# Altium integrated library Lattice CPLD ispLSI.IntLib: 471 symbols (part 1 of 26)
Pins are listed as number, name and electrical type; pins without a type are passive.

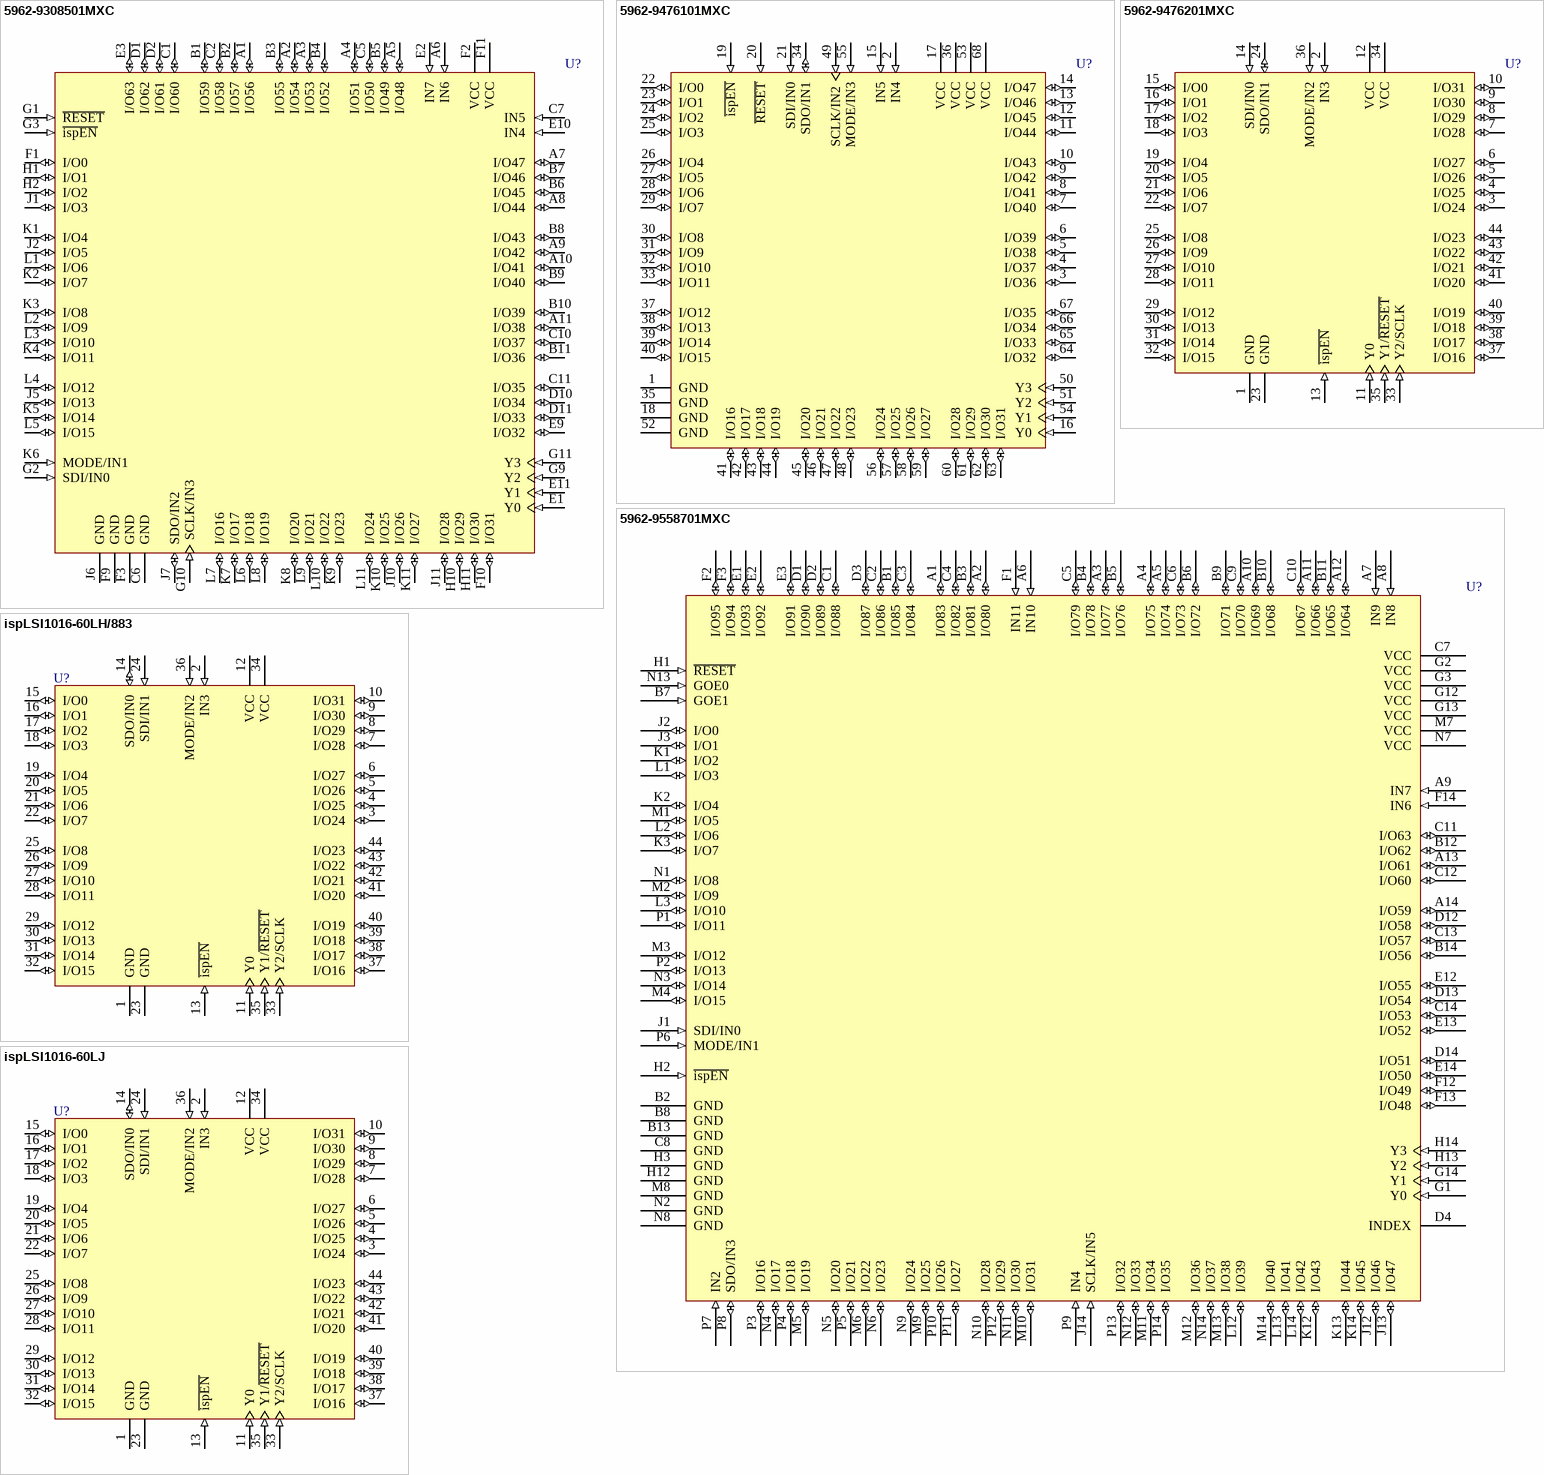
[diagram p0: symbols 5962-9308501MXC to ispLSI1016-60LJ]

## 5962-9308501MXC
designator U?
In-System Programmable High-Density PLD; Note: Pins G2, K6, J7 and G10 have dual function capability.; Note: SMD Number shown, corresponds to Device
footprint CPGA84 (PGA, 85-Leads, Body 29.5x29.5mm, Pitch 2.54mm)
3D model 1032-CPGA84 (85-Pin Pin Grid Array 2.54 mm Pitch)
pins: A1 I/O56 (io), A2 I/O54 (io), A3 I/O53 (io), A4 I/O51 (io), A5 I/O48 (io), A6 IN6 (in), A7 I/O47 (io), A8 I/O44 (io), A9 I/O42 (io), A10 I/O41 (io), A11 I/O38 (io), B1 I/O59 (io), B2 I/O57 (io), B3 I/O55 (io), B4 I/O52 (io), B5 I/O49 (io), B6 I/O45 (io), B7 I/O46 (io), B8 I/O43 (io), B9 I/O40 (io), B10 I/O39 (io), B11 I/O36 (io), C1 I/O60 (io), C2 I/O58 (io), C5 I/O50 (io), C6 GND (power), C7 IN5 (in), C10 I/O37 (io), C11 I/O35 (io), D1 I/O62 (io), D2 I/O61 (io), D10 I/O34 (io), D11 I/O33 (io), E1 Y0 (in), E2 IN7 (in), E3 I/O63 (io), E9 I/O32 (io), E10 IN4 (in), E11 Y1 (in), F1 I/O0 (io), F2 VCC (power), F3 GND (power), F9 GND (power), F10 I/O31 (io), F11 VCC (power), G1 ~{RESET} (in), G2 SDI/IN0 (in), G3 ~{ispEN} (in), G9 Y2 (in), G10 SCLK/IN3 (in), G11 Y3 (in), H1 I/O1 (io), H2 I/O2 (io), H10 I/O29 (io), H11 I/O30 (io), J1 I/O3 (io), J2 I/O5 (io), J5 I/O13 (io), J6 GND (power), J7 SDO/IN2 (io), J10 I/O26 (io), J11 I/O28 (io), K1 I/O4 (io), K2 I/O7 (io), K3 I/O8 (io), K4 I/O11 (io), K5 I/O14 (io), K6 MODE/IN1 (in), K7 I/O17 (io), K8 I/O20 (io), K9 I/O23 (io), K10 I/O25 (io), K11 I/O27 (io), L1 I/O6 (io), L2 I/O9 (io), L3 I/O10 (io), L4 I/O12 (io), L5 I/O15 (io), L6 I/O18 (io), L7 I/O16 (io), L8 I/O19 (io), L9 I/O21 (io), L10 I/O22 (io), L11 I/O24 (io)

## 5962-9476101MXC
designator U?
In-System Programmable High-Density PLD; Note: Pins 21, 34, 49 and 55 have dual function capability.; Note: SMD Number shown, corresponds to Device
footprint JLCC68_N (Leaded Chip Carrier, 68-Leads, Body 24x24mm, Pitch 1.27mm, IPC Medium Density)
footprint JLCC68_L (Leaded Chip Carrier, 68-Leads, Body 24x24mm, Pitch 1.27mm, IPC High Density)
footprint JLCC68_M (Leaded Chip Carrier, 68-Leads, Body 24x24mm, Pitch 1.27mm, IPC Low Density)
3D model 1024-JLCC68 (68-Pin Leaded Chip Carrier 1.27 mm Pitch)
pins: 1 GND (power), 2 IN4 (in), 3 I/O36 (io), 4 I/O37 (io), 5 I/O38 (io), 6 I/O39 (io), 7 I/O40 (io), 8 I/O41 (io), 9 I/O42 (io), 10 I/O43 (io), 11 I/O44 (io), 12 I/O45 (io), 13 I/O46 (io), 14 I/O47 (io), 15 IN5 (in), 16 Y0 (in), 17 VCC (power), 18 GND (power), 19 ~{ispEN} (in), 20 ~{RESET} (in), 21 SDI/IN0 (in), 22 I/O0 (io), 23 I/O1 (io), 24 I/O2 (io), 25 I/O3 (io), 26 I/O4 (io), 27 I/O5 (io), 28 I/O6 (io), 29 I/O7 (io), 30 I/O8 (io), 31 I/O9 (io), 32 I/O10 (io), 33 I/O11 (io), 34 SDO/IN1 (io), 35 GND (power), 36 VCC (power), 37 I/O12 (io), 38 I/O13 (io), 39 I/O14 (io), 40 I/O15 (io), 41 I/O16 (io), 42 I/O17 (io), 43 I/O18 (io), 44 I/O19 (io), 45 I/O20 (io), 46 I/O21 (io), 47 I/O22 (io), 48 I/O23 (io), 49 SCLK/IN2 (in), 50 Y3 (in), 51 Y2 (in), 52 GND (power), 53 VCC (power), 54 Y1 (in), 55 MODE/IN3 (in), 56 I/O24 (io), 57 I/O25 (io), 58 I/O26 (io), 59 I/O27 (io), 60 I/O28 (io), 61 I/O29 (io), 62 I/O30 (io), 63 I/O31 (io), 64 I/O32 (io), 65 I/O33 (io), 66 I/O34 (io), 67 I/O35 (io), 68 VCC (power)

## 5962-9476201MXC
designator U?
In-System Programmable High-Density PLD; Note: Pins 14, 24, 33 and 36 have dual function capability.; Note: SMD Number shown, corresponds to Device ispLSI 1016-60LH/883
footprint JLCC44_N (Leaded Chip Carrier, 44-Leads, Body 16.3x16.3mm, Pitch 1.27mm, IPC Medium Density)
footprint JLCC44_L (Leaded Chip Carrier, 44-Leads, Body 16.3x16.3mm, Pitch 1.27mm, IPC High Density)
footprint JLCC44_M (Leaded Chip Carrier, 44-Leads, Body 16.3x16.3mm, Pitch 1.27mm, IPC Low Density)
3D model 1016-JLCC44 (44-Pin Leaded Chip Carrier 1.27 mm Pitch)
pins: 1 GND (power), 2 IN3 (in), 3 I/O24 (io), 4 I/O25 (io), 5 I/O26 (io), 6 I/O27 (io), 7 I/O28 (io), 8 I/O29 (io), 9 I/O30 (io), 10 I/O31 (io), 11 Y0 (in), 12 VCC (power), 13 ~{ispEN} (in), 14 SDI/IN0 (in), 15 I/O0 (io), 16 I/O1 (io), 17 I/O2 (io), 18 I/O3 (io), 19 I/O4 (io), 20 I/O5 (io), 21 I/O6 (io), 22 I/O7 (io), 23 GND (power), 24 SDO/IN1 (io), 25 I/O8 (io), 26 I/O9 (io), 27 I/O10 (io), 28 I/O11 (io), 29 I/O12 (io), 30 I/O13 (io), 31 I/O14 (io), 32 I/O15 (io), 33 Y2/SCLK (in), 34 VCC (power), 35 Y1/~{RESET} (in), 36 MODE/IN2 (in), 37 I/O16 (io), 38 I/O17 (io), 39 I/O18 (io), 40 I/O19 (io), 41 I/O20 (io), 42 I/O21 (io), 43 I/O22 (io), 44 I/O23 (io)

## 5962-9558701MXC
designator U?
In-System Programmable High-Density PLD; Note: Pins J1, P6, P8 and J14 have dual function capability.; Note: SMD Number shown, corresponds to Device
footprint CPGA133 (PGA, 133-Leads, Body 37x37mm, Pitch 2.54mm)
3D model 1048C-CPGA133 (133-Pin Pin Grid Array 2.54 mm Pitch)
pins: A1 I/O83 (io), A2 I/O80 (io), A3 I/O77 (io), A4 I/O75 (io), A5 I/O74 (io), A6 IN10 (in), A7 IN9 (in), A8 IN8 (in), A9 IN7 (in), A10 I/O69 (io), A11 I/O66 (io), A12 I/O64 (io), A13 I/O61 (io), A14 I/O59 (io), B1 I/O85 (io), B2 GND (power), B3 I/O81 (io), B4 I/O78 (io), B5 I/O76 (io), B6 I/O72 (io), B7 GOE1 (in), B8 GND (power), B9 I/O71 (io), B10 I/O68 (io), B11 I/O65 (io), B12 I/O62 (io), B13 GND (power), B14 I/O56 (io), C1 I/O88 (io), C2 I/O86 (io), C3 I/O84 (io), C4 I/O82 (io), C5 I/O79 (io), C6 I/O73 (io), C7 VCC (power), C8 GND (power), C9 I/O70 (io), C10 I/O67 (io), C11 I/O63 (io), C12 I/O60 (io), C13 I/O57 (io), C14 I/O53 (io), D1 I/O90 (io), D2 I/O89 (io), D3 I/O87 (io), D4 INDEX, D12 I/O58 (io), D13 I/O54 (io), D14 I/O51 (io), E1 I/O93 (io), E2 I/O92 (io), E3 I/O91 (io), E12 I/O55 (io), E13 I/O52 (io), E14 I/O50 (io), F1 IN11 (in), F2 I/O95 (io), F3 I/O94 (io), F12 I/O49 (io), F13 I/O48 (io), F14 IN6 (in), G1 Y0 (in), G2 VCC (power), G3 VCC (power), G12 VCC (power), G13 VCC (power), G14 Y1 (in), H1 ~{RESET} (in), H2 ~{ispEN} (in), H3 GND (power), H12 GND (power), H13 Y2 (in), H14 Y3 (in), J1 SDI/IN0 (in), J2 I/O0 (io), J3 I/O1 (io), J12 I/O46 (io), J13 I/O47 (io), J14 SCLK/IN5 (in), K1 I/O2 (io), K2 I/O4 (io), K3 I/O7 (io), K12 I/O43 (io), K13 I/O44 (io), K14 I/O45 (io), L1 I/O3 (io), L2 I/O6 (io), L3 I/O10 (io), L12 I/O39 (io), L13 I/O41 (io), L14 I/O42 (io), M1 I/O5 (io), M2 I/O9 (io), M3 I/O12 (io), M4 I/O15 (io), M5 I/O19 (io), M6 I/O22 (io), M7 VCC (power), M8 GND (power), M9 I/O25 (io), M10 I/O31 (io), M11 I/O34 (io), M12 I/O36 (io), M13 I/O38 (io), M14 I/O40 (io), N1 I/O8 (io), N2 GND (power), N3 I/O14 (io), N4 I/O17 (io), N5 I/O20 (io), N6 I/O23 (io), N7 VCC (power), N8 GND (power), N9 I/O24 (io), N10 I/O28 (io), N11 I/O30 (io), N12 I/O33 (io), N13 GOE0 (in), N14 I/O37 (io), P1 I/O11 (io), P2 I/O13 (io), P3 I/O16 (io), P4 I/O18 (io), P5 I/O21 (io), P6 MODE/IN1 (in), P7 IN2 (in), P8 SDO/IN3 (io), P9 IN4 (in), P10 I/O26 (io), P11 I/O27 (io), P12 I/O29 (io), P13 I/O32 (io), P14 I/O35 (io)

## ispLSI1016-60LH/883
designator U?
High-Density Programmable Logic
footprint JLCC44_N (Leaded Chip Carrier, 44-Leads, Body 16.3x16.3mm, Pitch 1.27mm, IPC Medium Density)
footprint JLCC44_L (Leaded Chip Carrier, 44-Leads, Body 16.3x16.3mm, Pitch 1.27mm, IPC High Density)
footprint JLCC44_M (Leaded Chip Carrier, 44-Leads, Body 16.3x16.3mm, Pitch 1.27mm, IPC Low Density)
3D model 1016-JLCC44 (44-Pin Leaded Chip Carrier 1.27 mm Pitch)
pins: 1 GND (power), 2 IN3 (in), 3 I/O24 (io), 4 I/O25 (io), 5 I/O26 (io), 6 I/O27 (io), 7 I/O28 (io), 8 I/O29 (io), 9 I/O30 (io), 10 I/O31 (io), 11 Y0 (in), 12 VCC (power), 13 ~{ispEN} (in), 14 SDO/IN0 (io), 15 I/O0 (io), 16 I/O1 (io), 17 I/O2 (io), 18 I/O3 (io), 19 I/O4 (io), 20 I/O5 (io), 21 I/O6 (io), 22 I/O7 (io), 23 GND (power), 24 SDI/IN1 (in), 25 I/O8 (io), 26 I/O9 (io), 27 I/O10 (io), 28 I/O11 (io), 29 I/O12 (io), 30 I/O13 (io), 31 I/O14 (io), 32 I/O15 (io), 33 Y2/SCLK (in), 34 VCC (power), 35 Y1/~{RESET} (in), 36 MODE/IN2 (in), 37 I/O16 (io), 38 I/O17 (io), 39 I/O18 (io), 40 I/O19 (io), 41 I/O20 (io), 42 I/O21 (io), 43 I/O22 (io), 44 I/O23 (io)

## ispLSI1016-60LJ
designator U?
High-Density Programmable Logic
footprint PLCC44_N (Leaded Chip Carrier, 44-Leads, Body 16.6x16.6mm, Pitch 1.27mm, IPC Medium Density)
footprint PLCC44_L (Leaded Chip Carrier, 44-Leads, Body 16.6x16.6mm, Pitch 1.27mm, IPC High Density)
footprint PLCC44_M (Leaded Chip Carrier, 44-Leads, Body 16.6x16.6mm, Pitch 1.27mm, IPC Low Density)
3D model 1016-PLCC44 (44-Pin Leaded Chip Carrier 1.27 mm Pitch)
pins: 1 GND (power), 2 IN3 (in), 3 I/O24 (io), 4 I/O25 (io), 5 I/O26 (io), 6 I/O27 (io), 7 I/O28 (io), 8 I/O29 (io), 9 I/O30 (io), 10 I/O31 (io), 11 Y0 (in), 12 VCC (power), 13 ~{ispEN} (in), 14 SDO/IN0 (io), 15 I/O0 (io), 16 I/O1 (io), 17 I/O2 (io), 18 I/O3 (io), 19 I/O4 (io), 20 I/O5 (io), 21 I/O6 (io), 22 I/O7 (io), 23 GND (power), 24 SDI/IN1 (in), 25 I/O8 (io), 26 I/O9 (io), 27 I/O10 (io), 28 I/O11 (io), 29 I/O12 (io), 30 I/O13 (io), 31 I/O14 (io), 32 I/O15 (io), 33 Y2/SCLK (in), 34 VCC (power), 35 Y1/~{RESET} (in), 36 MODE/IN2 (in), 37 I/O16 (io), 38 I/O17 (io), 39 I/O18 (io), 40 I/O19 (io), 41 I/O20 (io), 42 I/O21 (io), 43 I/O22 (io), 44 I/O23 (io)

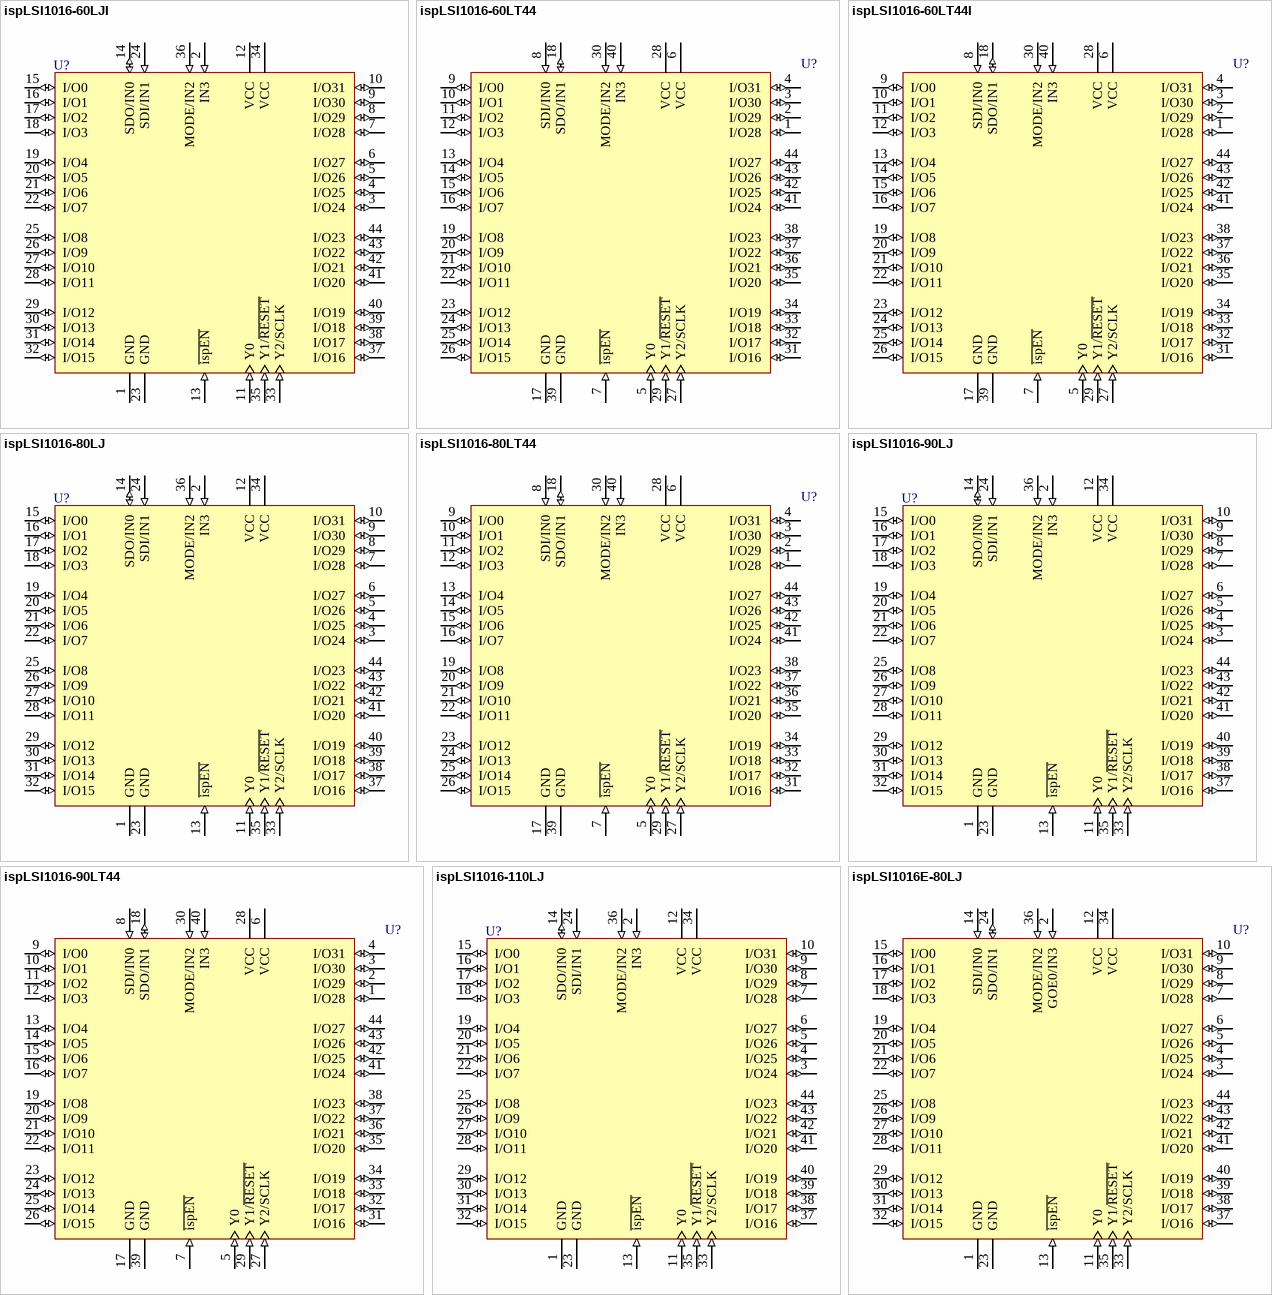
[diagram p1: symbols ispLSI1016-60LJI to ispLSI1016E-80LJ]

## ispLSI1016-60LJI
designator U?
High-Density Programmable Logic
footprint PLCC44_N (Leaded Chip Carrier, 44-Leads, Body 16.6x16.6mm, Pitch 1.27mm, IPC Medium Density)
footprint PLCC44_L (Leaded Chip Carrier, 44-Leads, Body 16.6x16.6mm, Pitch 1.27mm, IPC High Density)
footprint PLCC44_M (Leaded Chip Carrier, 44-Leads, Body 16.6x16.6mm, Pitch 1.27mm, IPC Low Density)
3D model 1016-PLCC44 (44-Pin Leaded Chip Carrier 1.27 mm Pitch)
pins: 1 GND (power), 2 IN3 (in), 3 I/O24 (io), 4 I/O25 (io), 5 I/O26 (io), 6 I/O27 (io), 7 I/O28 (io), 8 I/O29 (io), 9 I/O30 (io), 10 I/O31 (io), 11 Y0 (in), 12 VCC (power), 13 ~{ispEN} (in), 14 SDO/IN0 (io), 15 I/O0 (io), 16 I/O1 (io), 17 I/O2 (io), 18 I/O3 (io), 19 I/O4 (io), 20 I/O5 (io), 21 I/O6 (io), 22 I/O7 (io), 23 GND (power), 24 SDI/IN1 (in), 25 I/O8 (io), 26 I/O9 (io), 27 I/O10 (io), 28 I/O11 (io), 29 I/O12 (io), 30 I/O13 (io), 31 I/O14 (io), 32 I/O15 (io), 33 Y2/SCLK (in), 34 VCC (power), 35 Y1/~{RESET} (in), 36 MODE/IN2 (in), 37 I/O16 (io), 38 I/O17 (io), 39 I/O18 (io), 40 I/O19 (io), 41 I/O20 (io), 42 I/O21 (io), 43 I/O22 (io), 44 I/O23 (io)

## ispLSI1016-60LT44
designator U?
In-System Programmable High-Density PLD; Note: Pins 8, 18, 27 and 30 have dual function capability.
footprint TQFP44_N (Thin QFP, 44-Leads, Body 10x10mm, Pitch 0.8mm, IPC Medium Density)
footprint TQFP44_L (Thin QFP, 44-Leads, Body 10x10mm, Pitch 0.8mm, IPC High Density)
footprint TQFP44_M (Thin QFP, 44-Leads, Body 10x10mm, Pitch 0.8mm, IPC Low Density)
3D model 1016-TQFP44 (44-Pin Thin Quad Flat Pack 0.8 mm Pitch)
pins: 1 I/O28 (io), 2 I/O29 (io), 3 I/O30 (io), 4 I/O31 (io), 5 Y0 (in), 6 VCC (power), 7 ~{ispEN} (in), 8 SDI/IN0 (in), 9 I/O0 (io), 10 I/O1 (io), 11 I/O2 (io), 12 I/O3 (io), 13 I/O4 (io), 14 I/O5 (io), 15 I/O6 (io), 16 I/O7 (io), 17 GND (power), 18 SDO/IN1 (io), 19 I/O8 (io), 20 I/O9 (io), 21 I/O10 (io), 22 I/O11 (io), 23 I/O12 (io), 24 I/O13 (io), 25 I/O14 (io), 26 I/O15 (io), 27 Y2/SCLK (in), 28 VCC (power), 29 Y1/~{RESET} (in), 30 MODE/IN2 (in), 31 I/O16 (io), 32 I/O17 (io), 33 I/O18 (io), 34 I/O19 (io), 35 I/O20 (io), 36 I/O21 (io), 37 I/O22 (io), 38 I/O23 (io), 39 GND (power), 40 IN3 (in), 41 I/O24 (io), 42 I/O25 (io), 43 I/O26 (io), 44 I/O27 (io)

## ispLSI1016-60LT44I
designator U?
In-System Programmable High-Density PLD; Note: Pins 8, 18, 27 and 30 have dual function capability.
footprint TQFP44_N (Thin QFP, 44-Leads, Body 10x10mm, Pitch 0.8mm, IPC Medium Density)
footprint TQFP44_L (Thin QFP, 44-Leads, Body 10x10mm, Pitch 0.8mm, IPC High Density)
footprint TQFP44_M (Thin QFP, 44-Leads, Body 10x10mm, Pitch 0.8mm, IPC Low Density)
3D model 1016-TQFP44 (44-Pin Thin Quad Flat Pack 0.8 mm Pitch)
pins: 1 I/O28 (io), 2 I/O29 (io), 3 I/O30 (io), 4 I/O31 (io), 5 Y0 (in), 6 VCC (power), 7 ~{ispEN} (in), 8 SDI/IN0 (in), 9 I/O0 (io), 10 I/O1 (io), 11 I/O2 (io), 12 I/O3 (io), 13 I/O4 (io), 14 I/O5 (io), 15 I/O6 (io), 16 I/O7 (io), 17 GND (power), 18 SDO/IN1 (io), 19 I/O8 (io), 20 I/O9 (io), 21 I/O10 (io), 22 I/O11 (io), 23 I/O12 (io), 24 I/O13 (io), 25 I/O14 (io), 26 I/O15 (io), 27 Y2/SCLK (in), 28 VCC (power), 29 Y1/~{RESET} (in), 30 MODE/IN2 (in), 31 I/O16 (io), 32 I/O17 (io), 33 I/O18 (io), 34 I/O19 (io), 35 I/O20 (io), 36 I/O21 (io), 37 I/O22 (io), 38 I/O23 (io), 39 GND (power), 40 IN3 (in), 41 I/O24 (io), 42 I/O25 (io), 43 I/O26 (io), 44 I/O27 (io)

## ispLSI1016-80LJ
designator U?
High-Density Programmable Logic
footprint PLCC44_N (Leaded Chip Carrier, 44-Leads, Body 16.6x16.6mm, Pitch 1.27mm, IPC Medium Density)
footprint PLCC44_L (Leaded Chip Carrier, 44-Leads, Body 16.6x16.6mm, Pitch 1.27mm, IPC High Density)
footprint PLCC44_M (Leaded Chip Carrier, 44-Leads, Body 16.6x16.6mm, Pitch 1.27mm, IPC Low Density)
3D model 1016-PLCC44 (44-Pin Leaded Chip Carrier 1.27 mm Pitch)
pins: 1 GND (power), 2 IN3 (in), 3 I/O24 (io), 4 I/O25 (io), 5 I/O26 (io), 6 I/O27 (io), 7 I/O28 (io), 8 I/O29 (io), 9 I/O30 (io), 10 I/O31 (io), 11 Y0 (in), 12 VCC (power), 13 ~{ispEN} (in), 14 SDO/IN0 (io), 15 I/O0 (io), 16 I/O1 (io), 17 I/O2 (io), 18 I/O3 (io), 19 I/O4 (io), 20 I/O5 (io), 21 I/O6 (io), 22 I/O7 (io), 23 GND (power), 24 SDI/IN1 (in), 25 I/O8 (io), 26 I/O9 (io), 27 I/O10 (io), 28 I/O11 (io), 29 I/O12 (io), 30 I/O13 (io), 31 I/O14 (io), 32 I/O15 (io), 33 Y2/SCLK (in), 34 VCC (power), 35 Y1/~{RESET} (in), 36 MODE/IN2 (in), 37 I/O16 (io), 38 I/O17 (io), 39 I/O18 (io), 40 I/O19 (io), 41 I/O20 (io), 42 I/O21 (io), 43 I/O22 (io), 44 I/O23 (io)

## ispLSI1016-80LT44
designator U?
In-System Programmable High-Density PLD; Note: Pins 8, 18, 27 and 30 have dual function capability.
footprint TQFP44_N (Thin QFP, 44-Leads, Body 10x10mm, Pitch 0.8mm, IPC Medium Density)
footprint TQFP44_L (Thin QFP, 44-Leads, Body 10x10mm, Pitch 0.8mm, IPC High Density)
footprint TQFP44_M (Thin QFP, 44-Leads, Body 10x10mm, Pitch 0.8mm, IPC Low Density)
3D model 1016-TQFP44 (44-Pin Thin Quad Flat Pack 0.8 mm Pitch)
pins: 1 I/O28 (io), 2 I/O29 (io), 3 I/O30 (io), 4 I/O31 (io), 5 Y0 (in), 6 VCC (power), 7 ~{ispEN} (in), 8 SDI/IN0 (in), 9 I/O0 (io), 10 I/O1 (io), 11 I/O2 (io), 12 I/O3 (io), 13 I/O4 (io), 14 I/O5 (io), 15 I/O6 (io), 16 I/O7 (io), 17 GND (power), 18 SDO/IN1 (io), 19 I/O8 (io), 20 I/O9 (io), 21 I/O10 (io), 22 I/O11 (io), 23 I/O12 (io), 24 I/O13 (io), 25 I/O14 (io), 26 I/O15 (io), 27 Y2/SCLK (in), 28 VCC (power), 29 Y1/~{RESET} (in), 30 MODE/IN2 (in), 31 I/O16 (io), 32 I/O17 (io), 33 I/O18 (io), 34 I/O19 (io), 35 I/O20 (io), 36 I/O21 (io), 37 I/O22 (io), 38 I/O23 (io), 39 GND (power), 40 IN3 (in), 41 I/O24 (io), 42 I/O25 (io), 43 I/O26 (io), 44 I/O27 (io)

## ispLSI1016-90LJ
designator U?
High-Density Programmable Logic
footprint PLCC44_N (Leaded Chip Carrier, 44-Leads, Body 16.6x16.6mm, Pitch 1.27mm, IPC Medium Density)
footprint PLCC44_L (Leaded Chip Carrier, 44-Leads, Body 16.6x16.6mm, Pitch 1.27mm, IPC High Density)
footprint PLCC44_M (Leaded Chip Carrier, 44-Leads, Body 16.6x16.6mm, Pitch 1.27mm, IPC Low Density)
3D model 1016-PLCC44 (44-Pin Leaded Chip Carrier 1.27 mm Pitch)
pins: 1 GND (power), 2 IN3 (in), 3 I/O24 (io), 4 I/O25 (io), 5 I/O26 (io), 6 I/O27 (io), 7 I/O28 (io), 8 I/O29 (io), 9 I/O30 (io), 10 I/O31 (io), 11 Y0 (in), 12 VCC (power), 13 ~{ispEN} (in), 14 SDO/IN0 (io), 15 I/O0 (io), 16 I/O1 (io), 17 I/O2 (io), 18 I/O3 (io), 19 I/O4 (io), 20 I/O5 (io), 21 I/O6 (io), 22 I/O7 (io), 23 GND (power), 24 SDI/IN1 (in), 25 I/O8 (io), 26 I/O9 (io), 27 I/O10 (io), 28 I/O11 (io), 29 I/O12 (io), 30 I/O13 (io), 31 I/O14 (io), 32 I/O15 (io), 33 Y2/SCLK (in), 34 VCC (power), 35 Y1/~{RESET} (in), 36 MODE/IN2 (in), 37 I/O16 (io), 38 I/O17 (io), 39 I/O18 (io), 40 I/O19 (io), 41 I/O20 (io), 42 I/O21 (io), 43 I/O22 (io), 44 I/O23 (io)

## ispLSI1016-90LT44
designator U?
In-System Programmable High-Density PLD; Note: Pins 8, 18, 27 and 30 have dual function capability.
footprint TQFP44_N (Thin QFP, 44-Leads, Body 10x10mm, Pitch 0.8mm, IPC Medium Density)
footprint TQFP44_L (Thin QFP, 44-Leads, Body 10x10mm, Pitch 0.8mm, IPC High Density)
footprint TQFP44_M (Thin QFP, 44-Leads, Body 10x10mm, Pitch 0.8mm, IPC Low Density)
3D model 1016-TQFP44 (44-Pin Thin Quad Flat Pack 0.8 mm Pitch)
pins: 1 I/O28 (io), 2 I/O29 (io), 3 I/O30 (io), 4 I/O31 (io), 5 Y0 (in), 6 VCC (power), 7 ~{ispEN} (in), 8 SDI/IN0 (in), 9 I/O0 (io), 10 I/O1 (io), 11 I/O2 (io), 12 I/O3 (io), 13 I/O4 (io), 14 I/O5 (io), 15 I/O6 (io), 16 I/O7 (io), 17 GND (power), 18 SDO/IN1 (io), 19 I/O8 (io), 20 I/O9 (io), 21 I/O10 (io), 22 I/O11 (io), 23 I/O12 (io), 24 I/O13 (io), 25 I/O14 (io), 26 I/O15 (io), 27 Y2/SCLK (in), 28 VCC (power), 29 Y1/~{RESET} (in), 30 MODE/IN2 (in), 31 I/O16 (io), 32 I/O17 (io), 33 I/O18 (io), 34 I/O19 (io), 35 I/O20 (io), 36 I/O21 (io), 37 I/O22 (io), 38 I/O23 (io), 39 GND (power), 40 IN3 (in), 41 I/O24 (io), 42 I/O25 (io), 43 I/O26 (io), 44 I/O27 (io)

## ispLSI1016-110LJ
designator U?
High-Density Programmable Logic
footprint PLCC44_N (Leaded Chip Carrier, 44-Leads, Body 16.6x16.6mm, Pitch 1.27mm, IPC Medium Density)
footprint PLCC44_L (Leaded Chip Carrier, 44-Leads, Body 16.6x16.6mm, Pitch 1.27mm, IPC High Density)
footprint PLCC44_M (Leaded Chip Carrier, 44-Leads, Body 16.6x16.6mm, Pitch 1.27mm, IPC Low Density)
3D model 1016-PLCC44 (44-Pin Leaded Chip Carrier 1.27 mm Pitch)
pins: 1 GND (power), 2 IN3 (in), 3 I/O24 (io), 4 I/O25 (io), 5 I/O26 (io), 6 I/O27 (io), 7 I/O28 (io), 8 I/O29 (io), 9 I/O30 (io), 10 I/O31 (io), 11 Y0 (in), 12 VCC (power), 13 ~{ispEN} (in), 14 SDO/IN0 (io), 15 I/O0 (io), 16 I/O1 (io), 17 I/O2 (io), 18 I/O3 (io), 19 I/O4 (io), 20 I/O5 (io), 21 I/O6 (io), 22 I/O7 (io), 23 GND (power), 24 SDI/IN1 (in), 25 I/O8 (io), 26 I/O9 (io), 27 I/O10 (io), 28 I/O11 (io), 29 I/O12 (io), 30 I/O13 (io), 31 I/O14 (io), 32 I/O15 (io), 33 Y2/SCLK (in), 34 VCC (power), 35 Y1/~{RESET} (in), 36 MODE/IN2 (in), 37 I/O16 (io), 38 I/O17 (io), 39 I/O18 (io), 40 I/O19 (io), 41 I/O20 (io), 42 I/O21 (io), 43 I/O22 (io), 44 I/O23 (io)

## ispLSI1016E-80LJ
designator U?
In-System Programmable High-Density PLD; Note: Pins 2, 14, 24, 33 & 36 have dual function capability; Pin 2 is software selectable.
footprint PLCC44_N (Leaded Chip Carrier, 44-Leads, Body 16.6x16.6mm, Pitch 1.27mm, IPC Medium Density)
footprint PLCC44_L (Leaded Chip Carrier, 44-Leads, Body 16.6x16.6mm, Pitch 1.27mm, IPC High Density)
footprint PLCC44_M (Leaded Chip Carrier, 44-Leads, Body 16.6x16.6mm, Pitch 1.27mm, IPC Low Density)
3D model 1016E-PLCC44 (44-Pin Leaded Chip Carrier 1.27 mm Pitch)
pins: 1 GND (power), 2 GOE0/IN3 (in), 3 I/O24 (io), 4 I/O25 (io), 5 I/O26 (io), 6 I/O27 (io), 7 I/O28 (io), 8 I/O29 (io), 9 I/O30 (io), 10 I/O31 (io), 11 Y0 (in), 12 VCC (power), 13 ~{ispEN} (in), 14 SDI/IN0 (in), 15 I/O0 (io), 16 I/O1 (io), 17 I/O2 (io), 18 I/O3 (io), 19 I/O4 (io), 20 I/O5 (io), 21 I/O6 (io), 22 I/O7 (io), 23 GND (power), 24 SDO/IN1 (io), 25 I/O8 (io), 26 I/O9 (io), 27 I/O10 (io), 28 I/O11 (io), 29 I/O12 (io), 30 I/O13 (io), 31 I/O14 (io), 32 I/O15 (io), 33 Y2/SCLK (in), 34 VCC (power), 35 Y1/~{RESET} (in), 36 MODE/IN2 (in), 37 I/O16 (io), 38 I/O17 (io), 39 I/O18 (io), 40 I/O19 (io), 41 I/O20 (io), 42 I/O21 (io), 43 I/O22 (io), 44 I/O23 (io)

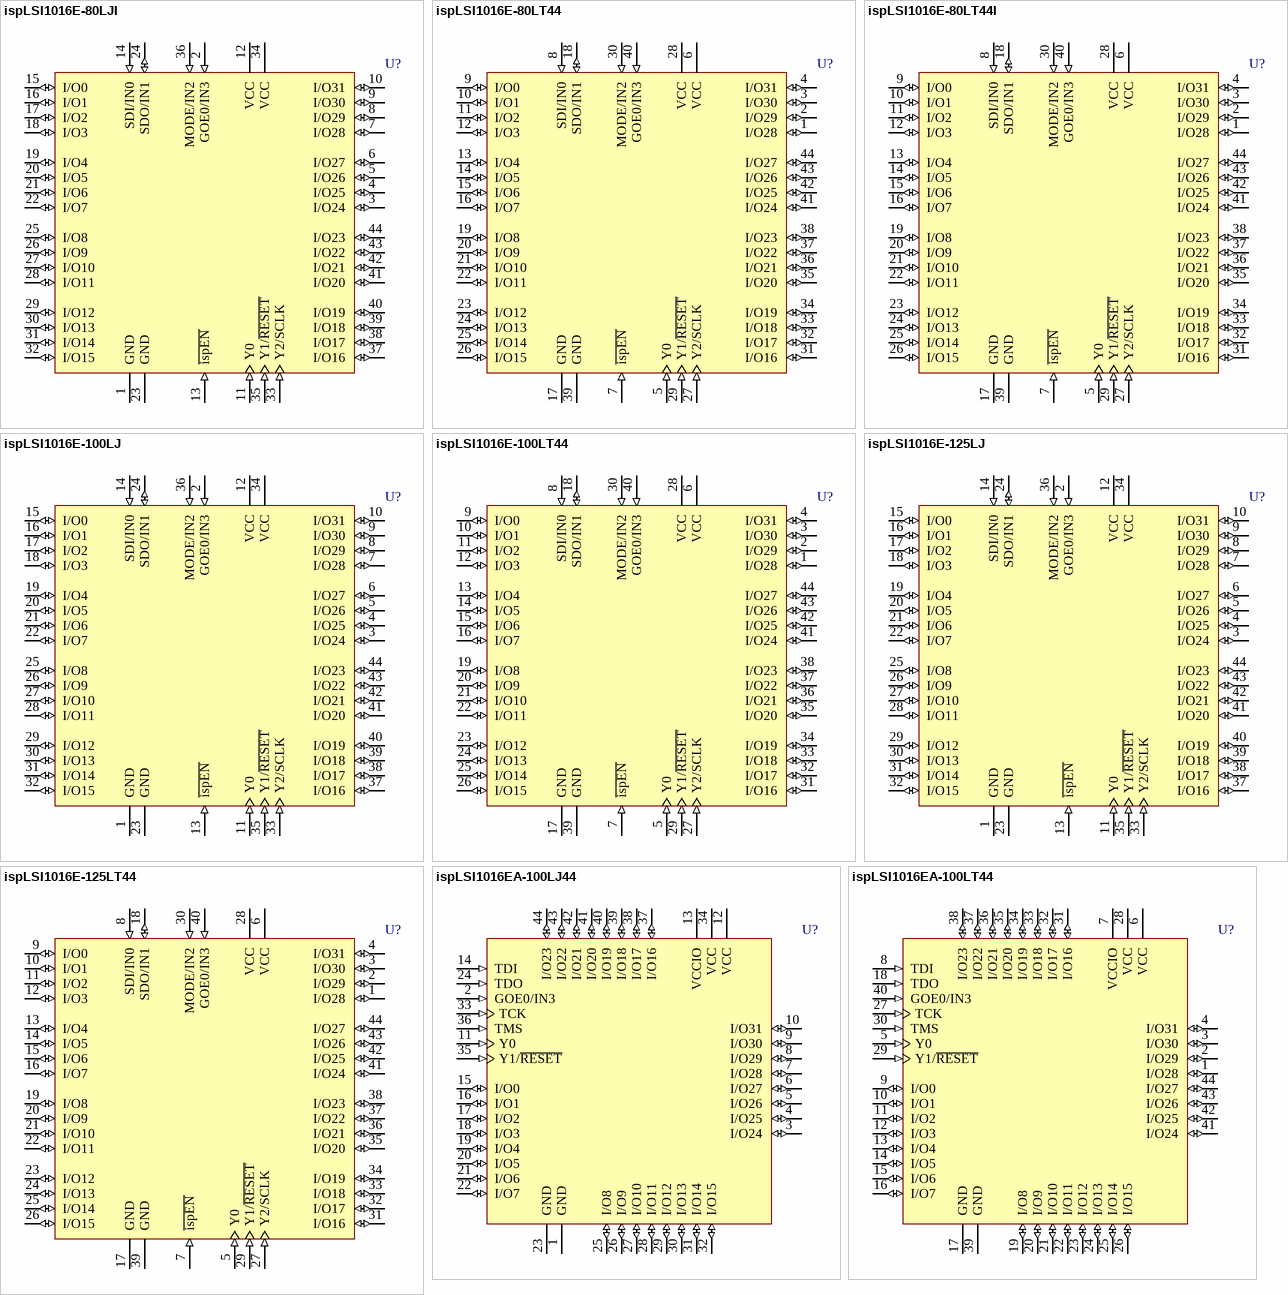
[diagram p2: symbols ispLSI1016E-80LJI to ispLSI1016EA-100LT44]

## ispLSI1016E-80LJI
designator U?
In-System Programmable High-Density PLD; Note: Pins 2, 14, 24, 33 & 36 have dual function capability; Pin 2 is software selectable.
footprint PLCC44_N (Leaded Chip Carrier, 44-Leads, Body 16.6x16.6mm, Pitch 1.27mm, IPC Medium Density)
footprint PLCC44_L (Leaded Chip Carrier, 44-Leads, Body 16.6x16.6mm, Pitch 1.27mm, IPC High Density)
footprint PLCC44_M (Leaded Chip Carrier, 44-Leads, Body 16.6x16.6mm, Pitch 1.27mm, IPC Low Density)
3D model 1016E-PLCC44 (44-Pin Leaded Chip Carrier 1.27 mm Pitch)
pins: 1 GND (power), 2 GOE0/IN3 (in), 3 I/O24 (io), 4 I/O25 (io), 5 I/O26 (io), 6 I/O27 (io), 7 I/O28 (io), 8 I/O29 (io), 9 I/O30 (io), 10 I/O31 (io), 11 Y0 (in), 12 VCC (power), 13 ~{ispEN} (in), 14 SDI/IN0 (in), 15 I/O0 (io), 16 I/O1 (io), 17 I/O2 (io), 18 I/O3 (io), 19 I/O4 (io), 20 I/O5 (io), 21 I/O6 (io), 22 I/O7 (io), 23 GND (power), 24 SDO/IN1 (io), 25 I/O8 (io), 26 I/O9 (io), 27 I/O10 (io), 28 I/O11 (io), 29 I/O12 (io), 30 I/O13 (io), 31 I/O14 (io), 32 I/O15 (io), 33 Y2/SCLK (in), 34 VCC (power), 35 Y1/~{RESET} (in), 36 MODE/IN2 (in), 37 I/O16 (io), 38 I/O17 (io), 39 I/O18 (io), 40 I/O19 (io), 41 I/O20 (io), 42 I/O21 (io), 43 I/O22 (io), 44 I/O23 (io)

## ispLSI1016E-80LT44
designator U?
In-System Programmable High-Density PLD; Note: Pins 8, 18, 27, 30 & 40 have dual function capability; Pin 40 is software selectable.
footprint TQFP44_N (Thin QFP, 44-Leads, Body 10x10mm, Pitch 0.8mm, IPC Medium Density)
footprint TQFP44_L (Thin QFP, 44-Leads, Body 10x10mm, Pitch 0.8mm, IPC High Density)
footprint TQFP44_M (Thin QFP, 44-Leads, Body 10x10mm, Pitch 0.8mm, IPC Low Density)
3D model 1016E-TQFP44 (44-Pin Thin Quad Flat Pack 0.8 mm Pitch)
pins: 1 I/O28 (io), 2 I/O29 (io), 3 I/O30 (io), 4 I/O31 (io), 5 Y0 (in), 6 VCC (power), 7 ~{ispEN} (in), 8 SDI/IN0 (in), 9 I/O0 (io), 10 I/O1 (io), 11 I/O2 (io), 12 I/O3 (io), 13 I/O4 (io), 14 I/O5 (io), 15 I/O6 (io), 16 I/O7 (io), 17 GND (power), 18 SDO/IN1 (io), 19 I/O8 (io), 20 I/O9 (io), 21 I/O10 (io), 22 I/O11 (io), 23 I/O12 (io), 24 I/O13 (io), 25 I/O14 (io), 26 I/O15 (io), 27 Y2/SCLK (in), 28 VCC (power), 29 Y1/~{RESET} (in), 30 MODE/IN2 (in), 31 I/O16 (io), 32 I/O17 (io), 33 I/O18 (io), 34 I/O19 (io), 35 I/O20 (io), 36 I/O21 (io), 37 I/O22 (io), 38 I/O23 (io), 39 GND (power), 40 GOE0/IN3 (in), 41 I/O24 (io), 42 I/O25 (io), 43 I/O26 (io), 44 I/O27 (io)

## ispLSI1016E-80LT44I
designator U?
In-System Programmable High-Density PLD; Note: Pins 8, 18, 27, 30 & 40 have dual function capability; Pin 40 is software selectable.
footprint TQFP44_N (Thin QFP, 44-Leads, Body 10x10mm, Pitch 0.8mm, IPC Medium Density)
footprint TQFP44_L (Thin QFP, 44-Leads, Body 10x10mm, Pitch 0.8mm, IPC High Density)
footprint TQFP44_M (Thin QFP, 44-Leads, Body 10x10mm, Pitch 0.8mm, IPC Low Density)
3D model 1016E-TQFP44 (44-Pin Thin Quad Flat Pack 0.8 mm Pitch)
pins: 1 I/O28 (io), 2 I/O29 (io), 3 I/O30 (io), 4 I/O31 (io), 5 Y0 (in), 6 VCC (power), 7 ~{ispEN} (in), 8 SDI/IN0 (in), 9 I/O0 (io), 10 I/O1 (io), 11 I/O2 (io), 12 I/O3 (io), 13 I/O4 (io), 14 I/O5 (io), 15 I/O6 (io), 16 I/O7 (io), 17 GND (power), 18 SDO/IN1 (io), 19 I/O8 (io), 20 I/O9 (io), 21 I/O10 (io), 22 I/O11 (io), 23 I/O12 (io), 24 I/O13 (io), 25 I/O14 (io), 26 I/O15 (io), 27 Y2/SCLK (in), 28 VCC (power), 29 Y1/~{RESET} (in), 30 MODE/IN2 (in), 31 I/O16 (io), 32 I/O17 (io), 33 I/O18 (io), 34 I/O19 (io), 35 I/O20 (io), 36 I/O21 (io), 37 I/O22 (io), 38 I/O23 (io), 39 GND (power), 40 GOE0/IN3 (in), 41 I/O24 (io), 42 I/O25 (io), 43 I/O26 (io), 44 I/O27 (io)

## ispLSI1016E-100LJ
designator U?
In-System Programmable High-Density PLD; Note: Pins 2, 14, 24, 33 & 36 have dual function capability; Pin 2 is software selectable.
footprint PLCC44_N (Leaded Chip Carrier, 44-Leads, Body 16.6x16.6mm, Pitch 1.27mm, IPC Medium Density)
footprint PLCC44_L (Leaded Chip Carrier, 44-Leads, Body 16.6x16.6mm, Pitch 1.27mm, IPC High Density)
footprint PLCC44_M (Leaded Chip Carrier, 44-Leads, Body 16.6x16.6mm, Pitch 1.27mm, IPC Low Density)
3D model 1016E-PLCC44 (44-Pin Leaded Chip Carrier 1.27 mm Pitch)
pins: 1 GND (power), 2 GOE0/IN3 (in), 3 I/O24 (io), 4 I/O25 (io), 5 I/O26 (io), 6 I/O27 (io), 7 I/O28 (io), 8 I/O29 (io), 9 I/O30 (io), 10 I/O31 (io), 11 Y0 (in), 12 VCC (power), 13 ~{ispEN} (in), 14 SDI/IN0 (in), 15 I/O0 (io), 16 I/O1 (io), 17 I/O2 (io), 18 I/O3 (io), 19 I/O4 (io), 20 I/O5 (io), 21 I/O6 (io), 22 I/O7 (io), 23 GND (power), 24 SDO/IN1 (io), 25 I/O8 (io), 26 I/O9 (io), 27 I/O10 (io), 28 I/O11 (io), 29 I/O12 (io), 30 I/O13 (io), 31 I/O14 (io), 32 I/O15 (io), 33 Y2/SCLK (in), 34 VCC (power), 35 Y1/~{RESET} (in), 36 MODE/IN2 (in), 37 I/O16 (io), 38 I/O17 (io), 39 I/O18 (io), 40 I/O19 (io), 41 I/O20 (io), 42 I/O21 (io), 43 I/O22 (io), 44 I/O23 (io)

## ispLSI1016E-100LT44
designator U?
In-System Programmable High-Density PLD; Note: Pins 8, 18, 27, 30 & 40 have dual function capability; Pin 40 is software selectable.
footprint TQFP44_N (Thin QFP, 44-Leads, Body 10x10mm, Pitch 0.8mm, IPC Medium Density)
footprint TQFP44_L (Thin QFP, 44-Leads, Body 10x10mm, Pitch 0.8mm, IPC High Density)
footprint TQFP44_M (Thin QFP, 44-Leads, Body 10x10mm, Pitch 0.8mm, IPC Low Density)
3D model 1016E-TQFP44 (44-Pin Thin Quad Flat Pack 0.8 mm Pitch)
pins: 1 I/O28 (io), 2 I/O29 (io), 3 I/O30 (io), 4 I/O31 (io), 5 Y0 (in), 6 VCC (power), 7 ~{ispEN} (in), 8 SDI/IN0 (in), 9 I/O0 (io), 10 I/O1 (io), 11 I/O2 (io), 12 I/O3 (io), 13 I/O4 (io), 14 I/O5 (io), 15 I/O6 (io), 16 I/O7 (io), 17 GND (power), 18 SDO/IN1 (io), 19 I/O8 (io), 20 I/O9 (io), 21 I/O10 (io), 22 I/O11 (io), 23 I/O12 (io), 24 I/O13 (io), 25 I/O14 (io), 26 I/O15 (io), 27 Y2/SCLK (in), 28 VCC (power), 29 Y1/~{RESET} (in), 30 MODE/IN2 (in), 31 I/O16 (io), 32 I/O17 (io), 33 I/O18 (io), 34 I/O19 (io), 35 I/O20 (io), 36 I/O21 (io), 37 I/O22 (io), 38 I/O23 (io), 39 GND (power), 40 GOE0/IN3 (in), 41 I/O24 (io), 42 I/O25 (io), 43 I/O26 (io), 44 I/O27 (io)

## ispLSI1016E-125LJ
designator U?
In-System Programmable High-Density PLD; Note: Pins 2, 14, 24, 33 & 36 have dual function capability; Pin 2 is software selectable.
footprint PLCC44_N (Leaded Chip Carrier, 44-Leads, Body 16.6x16.6mm, Pitch 1.27mm, IPC Medium Density)
footprint PLCC44_L (Leaded Chip Carrier, 44-Leads, Body 16.6x16.6mm, Pitch 1.27mm, IPC High Density)
footprint PLCC44_M (Leaded Chip Carrier, 44-Leads, Body 16.6x16.6mm, Pitch 1.27mm, IPC Low Density)
3D model 1016E-PLCC44 (44-Pin Leaded Chip Carrier 1.27 mm Pitch)
pins: 1 GND (power), 2 GOE0/IN3 (in), 3 I/O24 (io), 4 I/O25 (io), 5 I/O26 (io), 6 I/O27 (io), 7 I/O28 (io), 8 I/O29 (io), 9 I/O30 (io), 10 I/O31 (io), 11 Y0 (in), 12 VCC (power), 13 ~{ispEN} (in), 14 SDI/IN0 (in), 15 I/O0 (io), 16 I/O1 (io), 17 I/O2 (io), 18 I/O3 (io), 19 I/O4 (io), 20 I/O5 (io), 21 I/O6 (io), 22 I/O7 (io), 23 GND (power), 24 SDO/IN1 (io), 25 I/O8 (io), 26 I/O9 (io), 27 I/O10 (io), 28 I/O11 (io), 29 I/O12 (io), 30 I/O13 (io), 31 I/O14 (io), 32 I/O15 (io), 33 Y2/SCLK (in), 34 VCC (power), 35 Y1/~{RESET} (in), 36 MODE/IN2 (in), 37 I/O16 (io), 38 I/O17 (io), 39 I/O18 (io), 40 I/O19 (io), 41 I/O20 (io), 42 I/O21 (io), 43 I/O22 (io), 44 I/O23 (io)

## ispLSI1016E-125LT44
designator U?
In-System Programmable High-Density PLD; Note: Pins 8, 18, 27, 30 & 40 have dual function capability; Pin 40 is software selectable.
footprint TQFP44_N (Thin QFP, 44-Leads, Body 10x10mm, Pitch 0.8mm, IPC Medium Density)
footprint TQFP44_L (Thin QFP, 44-Leads, Body 10x10mm, Pitch 0.8mm, IPC High Density)
footprint TQFP44_M (Thin QFP, 44-Leads, Body 10x10mm, Pitch 0.8mm, IPC Low Density)
3D model 1016E-TQFP44 (44-Pin Thin Quad Flat Pack 0.8 mm Pitch)
pins: 1 I/O28 (io), 2 I/O29 (io), 3 I/O30 (io), 4 I/O31 (io), 5 Y0 (in), 6 VCC (power), 7 ~{ispEN} (in), 8 SDI/IN0 (in), 9 I/O0 (io), 10 I/O1 (io), 11 I/O2 (io), 12 I/O3 (io), 13 I/O4 (io), 14 I/O5 (io), 15 I/O6 (io), 16 I/O7 (io), 17 GND (power), 18 SDO/IN1 (io), 19 I/O8 (io), 20 I/O9 (io), 21 I/O10 (io), 22 I/O11 (io), 23 I/O12 (io), 24 I/O13 (io), 25 I/O14 (io), 26 I/O15 (io), 27 Y2/SCLK (in), 28 VCC (power), 29 Y1/~{RESET} (in), 30 MODE/IN2 (in), 31 I/O16 (io), 32 I/O17 (io), 33 I/O18 (io), 34 I/O19 (io), 35 I/O20 (io), 36 I/O21 (io), 37 I/O22 (io), 38 I/O23 (io), 39 GND (power), 40 GOE0/IN3 (in), 41 I/O24 (io), 42 I/O25 (io), 43 I/O26 (io), 44 I/O27 (io)

## ispLSI1016EA-100LJ44
designator U?
In-System Programmable High-Density PLD; Note: Pins 2 and 35 have dual function capability which is software selectable.
footprint PLCC44_N (Leaded Chip Carrier, 44-Leads, Body 16.6x16.6mm, Pitch 1.27mm, IPC Medium Density)
footprint PLCC44_L (Leaded Chip Carrier, 44-Leads, Body 16.6x16.6mm, Pitch 1.27mm, IPC High Density)
footprint PLCC44_M (Leaded Chip Carrier, 44-Leads, Body 16.6x16.6mm, Pitch 1.27mm, IPC Low Density)
3D model 1016EA-PLCC44 (44-Pin Leaded Chip Carrier 1.27 mm Pitch)
pins: 1 GND (power), 2 GOE0/IN3 (in), 3 I/O24 (io), 4 I/O25 (io), 5 I/O26 (io), 6 I/O27 (io), 7 I/O28 (io), 8 I/O29 (io), 9 I/O30 (io), 10 I/O31 (io), 11 Y0 (in), 12 VCC (power), 13 VCCIO (power), 14 TDI (in), 15 I/O0 (io), 16 I/O1 (io), 17 I/O2 (io), 18 I/O3 (io), 19 I/O4 (io), 20 I/O5 (io), 21 I/O6 (io), 22 I/O7 (io), 23 GND (power), 24 TDO (in), 25 I/O8 (io), 26 I/O9 (io), 27 I/O10 (io), 28 I/O11 (io), 29 I/O12 (io), 30 I/O13 (io), 31 I/O14 (io), 32 I/O15 (io), 33 TCK (in), 34 VCC (power), 35 Y1/~{RESET} (in), 36 TMS (in), 37 I/O16 (io), 38 I/O17 (io), 39 I/O18 (io), 40 I/O19 (io), 41 I/O20 (io), 42 I/O21 (io), 43 I/O22 (io), 44 I/O23 (io)

## ispLSI1016EA-100LT44
designator U?
In-System Programmable High-Density PLD; Note: Pins 2 and 35 have dual function capability which is software selectable.
footprint TQFP44_N (Thin QFP, 44-Leads, Body 10x10mm, Pitch 0.8mm, IPC Medium Density)
footprint TQFP44_L (Thin QFP, 44-Leads, Body 10x10mm, Pitch 0.8mm, IPC High Density)
footprint TQFP44_M (Thin QFP, 44-Leads, Body 10x10mm, Pitch 0.8mm, IPC Low Density)
3D model 1016EA-TQFP44 (44-Pin Thin Quad Flat Pack 0.8 mm Pitch)
pins: 1 I/O28 (io), 2 I/O29 (io), 3 I/O30 (io), 4 I/O31 (io), 5 Y0 (in), 6 VCC (power), 7 VCCIO (power), 8 TDI (in), 9 I/O0 (io), 10 I/O1 (io), 11 I/O2 (io), 12 I/O3 (io), 13 I/O4 (io), 14 I/O5 (io), 15 I/O6 (io), 16 I/O7 (io), 17 GND (power), 18 TDO (in), 19 I/O8 (io), 20 I/O9 (io), 21 I/O10 (io), 22 I/O11 (io), 23 I/O12 (io), 24 I/O13 (io), 25 I/O14 (io), 26 I/O15 (io), 27 TCK (in), 28 VCC (power), 29 Y1/~{RESET} (in), 30 TMS (in), 31 I/O16 (io), 32 I/O17 (io), 33 I/O18 (io), 34 I/O19 (io), 35 I/O20 (io), 36 I/O21 (io), 37 I/O22 (io), 38 I/O23 (io), 39 GND (power), 40 GOE0/IN3 (in), 41 I/O24 (io), 42 I/O25 (io), 43 I/O26 (io), 44 I/O27 (io)

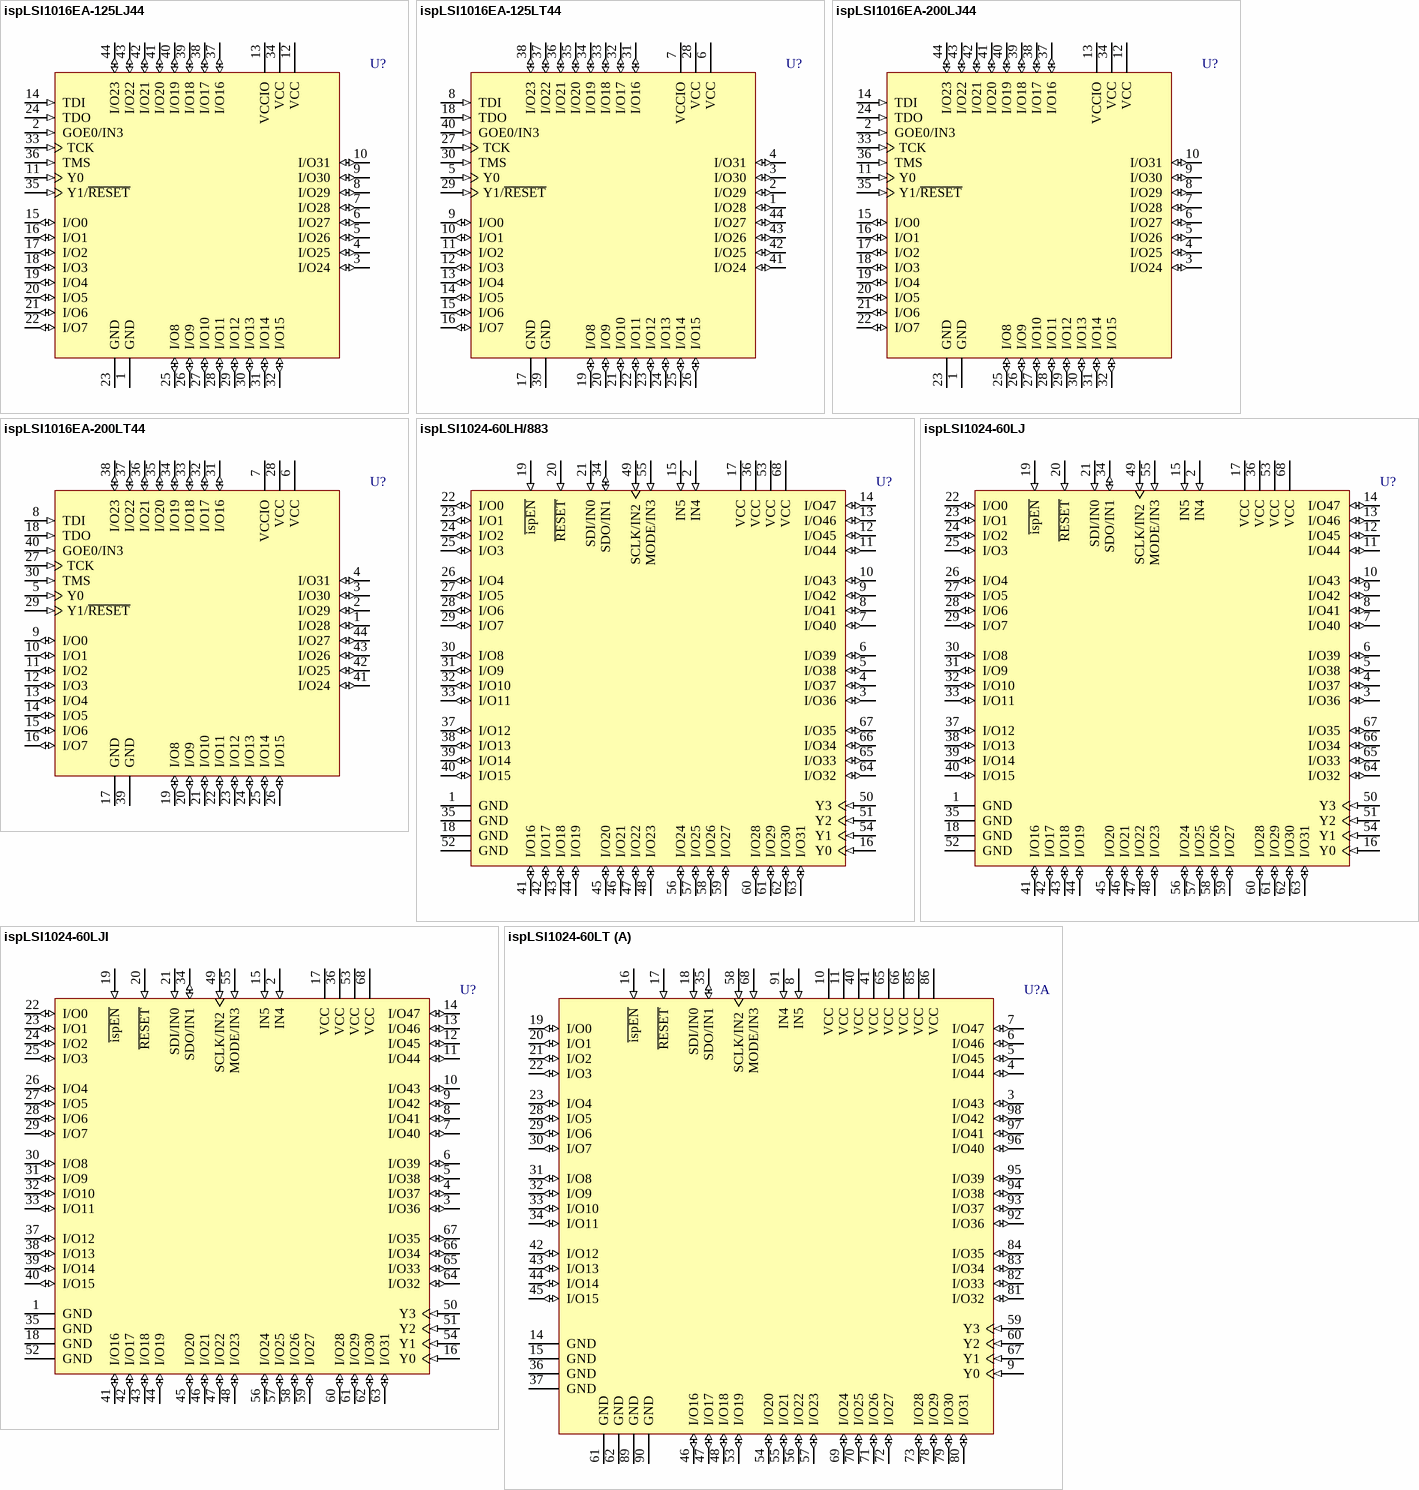
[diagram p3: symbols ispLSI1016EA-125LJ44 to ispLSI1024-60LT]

## ispLSI1016EA-125LJ44
designator U?
In-System Programmable High-Density PLD; Note: Pins 2 and 35 have dual function capability which is software selectable.
footprint PLCC44_N (Leaded Chip Carrier, 44-Leads, Body 16.6x16.6mm, Pitch 1.27mm, IPC Medium Density)
footprint PLCC44_L (Leaded Chip Carrier, 44-Leads, Body 16.6x16.6mm, Pitch 1.27mm, IPC High Density)
footprint PLCC44_M (Leaded Chip Carrier, 44-Leads, Body 16.6x16.6mm, Pitch 1.27mm, IPC Low Density)
3D model 1016EA-PLCC44 (44-Pin Leaded Chip Carrier 1.27 mm Pitch)
pins: 1 GND (power), 2 GOE0/IN3 (in), 3 I/O24 (io), 4 I/O25 (io), 5 I/O26 (io), 6 I/O27 (io), 7 I/O28 (io), 8 I/O29 (io), 9 I/O30 (io), 10 I/O31 (io), 11 Y0 (in), 12 VCC (power), 13 VCCIO (power), 14 TDI (in), 15 I/O0 (io), 16 I/O1 (io), 17 I/O2 (io), 18 I/O3 (io), 19 I/O4 (io), 20 I/O5 (io), 21 I/O6 (io), 22 I/O7 (io), 23 GND (power), 24 TDO (in), 25 I/O8 (io), 26 I/O9 (io), 27 I/O10 (io), 28 I/O11 (io), 29 I/O12 (io), 30 I/O13 (io), 31 I/O14 (io), 32 I/O15 (io), 33 TCK (in), 34 VCC (power), 35 Y1/~{RESET} (in), 36 TMS (in), 37 I/O16 (io), 38 I/O17 (io), 39 I/O18 (io), 40 I/O19 (io), 41 I/O20 (io), 42 I/O21 (io), 43 I/O22 (io), 44 I/O23 (io)

## ispLSI1016EA-125LT44
designator U?
In-System Programmable High-Density PLD; Note: Pins 2 and 35 have dual function capability which is software selectable.
footprint TQFP44_N (Thin QFP, 44-Leads, Body 10x10mm, Pitch 0.8mm, IPC Medium Density)
footprint TQFP44_L (Thin QFP, 44-Leads, Body 10x10mm, Pitch 0.8mm, IPC High Density)
footprint TQFP44_M (Thin QFP, 44-Leads, Body 10x10mm, Pitch 0.8mm, IPC Low Density)
3D model 1016EA-TQFP44 (44-Pin Thin Quad Flat Pack 0.8 mm Pitch)
pins: 1 I/O28 (io), 2 I/O29 (io), 3 I/O30 (io), 4 I/O31 (io), 5 Y0 (in), 6 VCC (power), 7 VCCIO (power), 8 TDI (in), 9 I/O0 (io), 10 I/O1 (io), 11 I/O2 (io), 12 I/O3 (io), 13 I/O4 (io), 14 I/O5 (io), 15 I/O6 (io), 16 I/O7 (io), 17 GND (power), 18 TDO (in), 19 I/O8 (io), 20 I/O9 (io), 21 I/O10 (io), 22 I/O11 (io), 23 I/O12 (io), 24 I/O13 (io), 25 I/O14 (io), 26 I/O15 (io), 27 TCK (in), 28 VCC (power), 29 Y1/~{RESET} (in), 30 TMS (in), 31 I/O16 (io), 32 I/O17 (io), 33 I/O18 (io), 34 I/O19 (io), 35 I/O20 (io), 36 I/O21 (io), 37 I/O22 (io), 38 I/O23 (io), 39 GND (power), 40 GOE0/IN3 (in), 41 I/O24 (io), 42 I/O25 (io), 43 I/O26 (io), 44 I/O27 (io)

## ispLSI1016EA-200LJ44
designator U?
In-System Programmable High-Density PLD; Note: Pins 2 and 35 have dual function capability which is software selectable.
footprint PLCC44_N (Leaded Chip Carrier, 44-Leads, Body 16.6x16.6mm, Pitch 1.27mm, IPC Medium Density)
footprint PLCC44_L (Leaded Chip Carrier, 44-Leads, Body 16.6x16.6mm, Pitch 1.27mm, IPC High Density)
footprint PLCC44_M (Leaded Chip Carrier, 44-Leads, Body 16.6x16.6mm, Pitch 1.27mm, IPC Low Density)
3D model 1016EA-PLCC44 (44-Pin Leaded Chip Carrier 1.27 mm Pitch)
pins: 1 GND (power), 2 GOE0/IN3 (in), 3 I/O24 (io), 4 I/O25 (io), 5 I/O26 (io), 6 I/O27 (io), 7 I/O28 (io), 8 I/O29 (io), 9 I/O30 (io), 10 I/O31 (io), 11 Y0 (in), 12 VCC (power), 13 VCCIO (power), 14 TDI (in), 15 I/O0 (io), 16 I/O1 (io), 17 I/O2 (io), 18 I/O3 (io), 19 I/O4 (io), 20 I/O5 (io), 21 I/O6 (io), 22 I/O7 (io), 23 GND (power), 24 TDO (in), 25 I/O8 (io), 26 I/O9 (io), 27 I/O10 (io), 28 I/O11 (io), 29 I/O12 (io), 30 I/O13 (io), 31 I/O14 (io), 32 I/O15 (io), 33 TCK (in), 34 VCC (power), 35 Y1/~{RESET} (in), 36 TMS (in), 37 I/O16 (io), 38 I/O17 (io), 39 I/O18 (io), 40 I/O19 (io), 41 I/O20 (io), 42 I/O21 (io), 43 I/O22 (io), 44 I/O23 (io)

## ispLSI1016EA-200LT44
designator U?
In-System Programmable High-Density PLD; Note: Pins 2 and 35 have dual function capability which is software selectable.
footprint TQFP44_N (Thin QFP, 44-Leads, Body 10x10mm, Pitch 0.8mm, IPC Medium Density)
footprint TQFP44_L (Thin QFP, 44-Leads, Body 10x10mm, Pitch 0.8mm, IPC High Density)
footprint TQFP44_M (Thin QFP, 44-Leads, Body 10x10mm, Pitch 0.8mm, IPC Low Density)
3D model 1016EA-TQFP44 (44-Pin Thin Quad Flat Pack 0.8 mm Pitch)
pins: 1 I/O28 (io), 2 I/O29 (io), 3 I/O30 (io), 4 I/O31 (io), 5 Y0 (in), 6 VCC (power), 7 VCCIO (power), 8 TDI (in), 9 I/O0 (io), 10 I/O1 (io), 11 I/O2 (io), 12 I/O3 (io), 13 I/O4 (io), 14 I/O5 (io), 15 I/O6 (io), 16 I/O7 (io), 17 GND (power), 18 TDO (in), 19 I/O8 (io), 20 I/O9 (io), 21 I/O10 (io), 22 I/O11 (io), 23 I/O12 (io), 24 I/O13 (io), 25 I/O14 (io), 26 I/O15 (io), 27 TCK (in), 28 VCC (power), 29 Y1/~{RESET} (in), 30 TMS (in), 31 I/O16 (io), 32 I/O17 (io), 33 I/O18 (io), 34 I/O19 (io), 35 I/O20 (io), 36 I/O21 (io), 37 I/O22 (io), 38 I/O23 (io), 39 GND (power), 40 GOE0/IN3 (in), 41 I/O24 (io), 42 I/O25 (io), 43 I/O26 (io), 44 I/O27 (io)

## ispLSI1024-60LH/883
designator U?
High-Density Programmable Logic
footprint JLCC68_N (Leaded Chip Carrier, 68-Leads, Body 24x24mm, Pitch 1.27mm, IPC Medium Density)
footprint JLCC68_L (Leaded Chip Carrier, 68-Leads, Body 24x24mm, Pitch 1.27mm, IPC High Density)
footprint JLCC68_M (Leaded Chip Carrier, 68-Leads, Body 24x24mm, Pitch 1.27mm, IPC Low Density)
3D model 1024-JLCC68 (68-Pin Leaded Chip Carrier 1.27 mm Pitch)
pins: 1 GND (power), 2 IN4 (in), 3 I/O36 (io), 4 I/O37 (io), 5 I/O38 (io), 6 I/O39 (io), 7 I/O40 (io), 8 I/O41 (io), 9 I/O42 (io), 10 I/O43 (io), 11 I/O44 (io), 12 I/O45 (io), 13 I/O46 (io), 14 I/O47 (io), 15 IN5 (in), 16 Y0 (in), 17 VCC (power), 18 GND (power), 19 ~{ispEN} (in), 20 ~{RESET} (in), 21 SDI/IN0 (in), 22 I/O0 (io), 23 I/O1 (io), 24 I/O2 (io), 25 I/O3 (io), 26 I/O4 (io), 27 I/O5 (io), 28 I/O6 (io), 29 I/O7 (io), 30 I/O8 (io), 31 I/O9 (io), 32 I/O10 (io), 33 I/O11 (io), 34 SDO/IN1 (io), 35 GND (power), 36 VCC (power), 37 I/O12 (io), 38 I/O13 (io), 39 I/O14 (io), 40 I/O15 (io), 41 I/O16 (io), 42 I/O17 (io), 43 I/O18 (io), 44 I/O19 (io), 45 I/O20 (io), 46 I/O21 (io), 47 I/O22 (io), 48 I/O23 (io), 49 SCLK/IN2 (in), 50 Y3 (in), 51 Y2 (in), 52 GND (power), 53 VCC (power), 54 Y1 (in), 55 MODE/IN3 (in), 56 I/O24 (io), 57 I/O25 (io), 58 I/O26 (io), 59 I/O27 (io), 60 I/O28 (io), 61 I/O29 (io), 62 I/O30 (io), 63 I/O31 (io), 64 I/O32 (io), 65 I/O33 (io), 66 I/O34 (io), 67 I/O35 (io), 68 VCC (power)

## ispLSI1024-60LJ
designator U?
High-Density Programmable Logic
footprint PLCC68_N (Leaded Chip Carrier, 68-Leads, Body 24x24mm, Pitch 1.27mm, IPC Medium Density)
footprint PLCC68_L (Leaded Chip Carrier, 68-Leads, Body 24x24mm, Pitch 1.27mm, IPC High Density)
footprint PLCC68_M (Leaded Chip Carrier, 68-Leads, Body 24x24mm, Pitch 1.27mm, IPC Low Density)
3D model 1024-PLCC68 (68-Pin Leaded Chip Carrier 1.27 mm Pitch)
pins: 1 GND (power), 2 IN4 (in), 3 I/O36 (io), 4 I/O37 (io), 5 I/O38 (io), 6 I/O39 (io), 7 I/O40 (io), 8 I/O41 (io), 9 I/O42 (io), 10 I/O43 (io), 11 I/O44 (io), 12 I/O45 (io), 13 I/O46 (io), 14 I/O47 (io), 15 IN5 (in), 16 Y0 (in), 17 VCC (power), 18 GND (power), 19 ~{ispEN} (in), 20 ~{RESET} (in), 21 SDI/IN0 (in), 22 I/O0 (io), 23 I/O1 (io), 24 I/O2 (io), 25 I/O3 (io), 26 I/O4 (io), 27 I/O5 (io), 28 I/O6 (io), 29 I/O7 (io), 30 I/O8 (io), 31 I/O9 (io), 32 I/O10 (io), 33 I/O11 (io), 34 SDO/IN1 (io), 35 GND (power), 36 VCC (power), 37 I/O12 (io), 38 I/O13 (io), 39 I/O14 (io), 40 I/O15 (io), 41 I/O16 (io), 42 I/O17 (io), 43 I/O18 (io), 44 I/O19 (io), 45 I/O20 (io), 46 I/O21 (io), 47 I/O22 (io), 48 I/O23 (io), 49 SCLK/IN2 (in), 50 Y3 (in), 51 Y2 (in), 52 GND (power), 53 VCC (power), 54 Y1 (in), 55 MODE/IN3 (in), 56 I/O24 (io), 57 I/O25 (io), 58 I/O26 (io), 59 I/O27 (io), 60 I/O28 (io), 61 I/O29 (io), 62 I/O30 (io), 63 I/O31 (io), 64 I/O32 (io), 65 I/O33 (io), 66 I/O34 (io), 67 I/O35 (io), 68 VCC (power)

## ispLSI1024-60LJI
designator U?
High-Density Programmable Logic
footprint PLCC68_N (Leaded Chip Carrier, 68-Leads, Body 24x24mm, Pitch 1.27mm, IPC Medium Density)
footprint PLCC68_L (Leaded Chip Carrier, 68-Leads, Body 24x24mm, Pitch 1.27mm, IPC High Density)
footprint PLCC68_M (Leaded Chip Carrier, 68-Leads, Body 24x24mm, Pitch 1.27mm, IPC Low Density)
3D model 1024-PLCC68 (68-Pin Leaded Chip Carrier 1.27 mm Pitch)
pins: 1 GND (power), 2 IN4 (in), 3 I/O36 (io), 4 I/O37 (io), 5 I/O38 (io), 6 I/O39 (io), 7 I/O40 (io), 8 I/O41 (io), 9 I/O42 (io), 10 I/O43 (io), 11 I/O44 (io), 12 I/O45 (io), 13 I/O46 (io), 14 I/O47 (io), 15 IN5 (in), 16 Y0 (in), 17 VCC (power), 18 GND (power), 19 ~{ispEN} (in), 20 ~{RESET} (in), 21 SDI/IN0 (in), 22 I/O0 (io), 23 I/O1 (io), 24 I/O2 (io), 25 I/O3 (io), 26 I/O4 (io), 27 I/O5 (io), 28 I/O6 (io), 29 I/O7 (io), 30 I/O8 (io), 31 I/O9 (io), 32 I/O10 (io), 33 I/O11 (io), 34 SDO/IN1 (io), 35 GND (power), 36 VCC (power), 37 I/O12 (io), 38 I/O13 (io), 39 I/O14 (io), 40 I/O15 (io), 41 I/O16 (io), 42 I/O17 (io), 43 I/O18 (io), 44 I/O19 (io), 45 I/O20 (io), 46 I/O21 (io), 47 I/O22 (io), 48 I/O23 (io), 49 SCLK/IN2 (in), 50 Y3 (in), 51 Y2 (in), 52 GND (power), 53 VCC (power), 54 Y1 (in), 55 MODE/IN3 (in), 56 I/O24 (io), 57 I/O25 (io), 58 I/O26 (io), 59 I/O27 (io), 60 I/O28 (io), 61 I/O29 (io), 62 I/O30 (io), 63 I/O31 (io), 64 I/O32 (io), 65 I/O33 (io), 66 I/O34 (io), 67 I/O35 (io), 68 VCC (power)

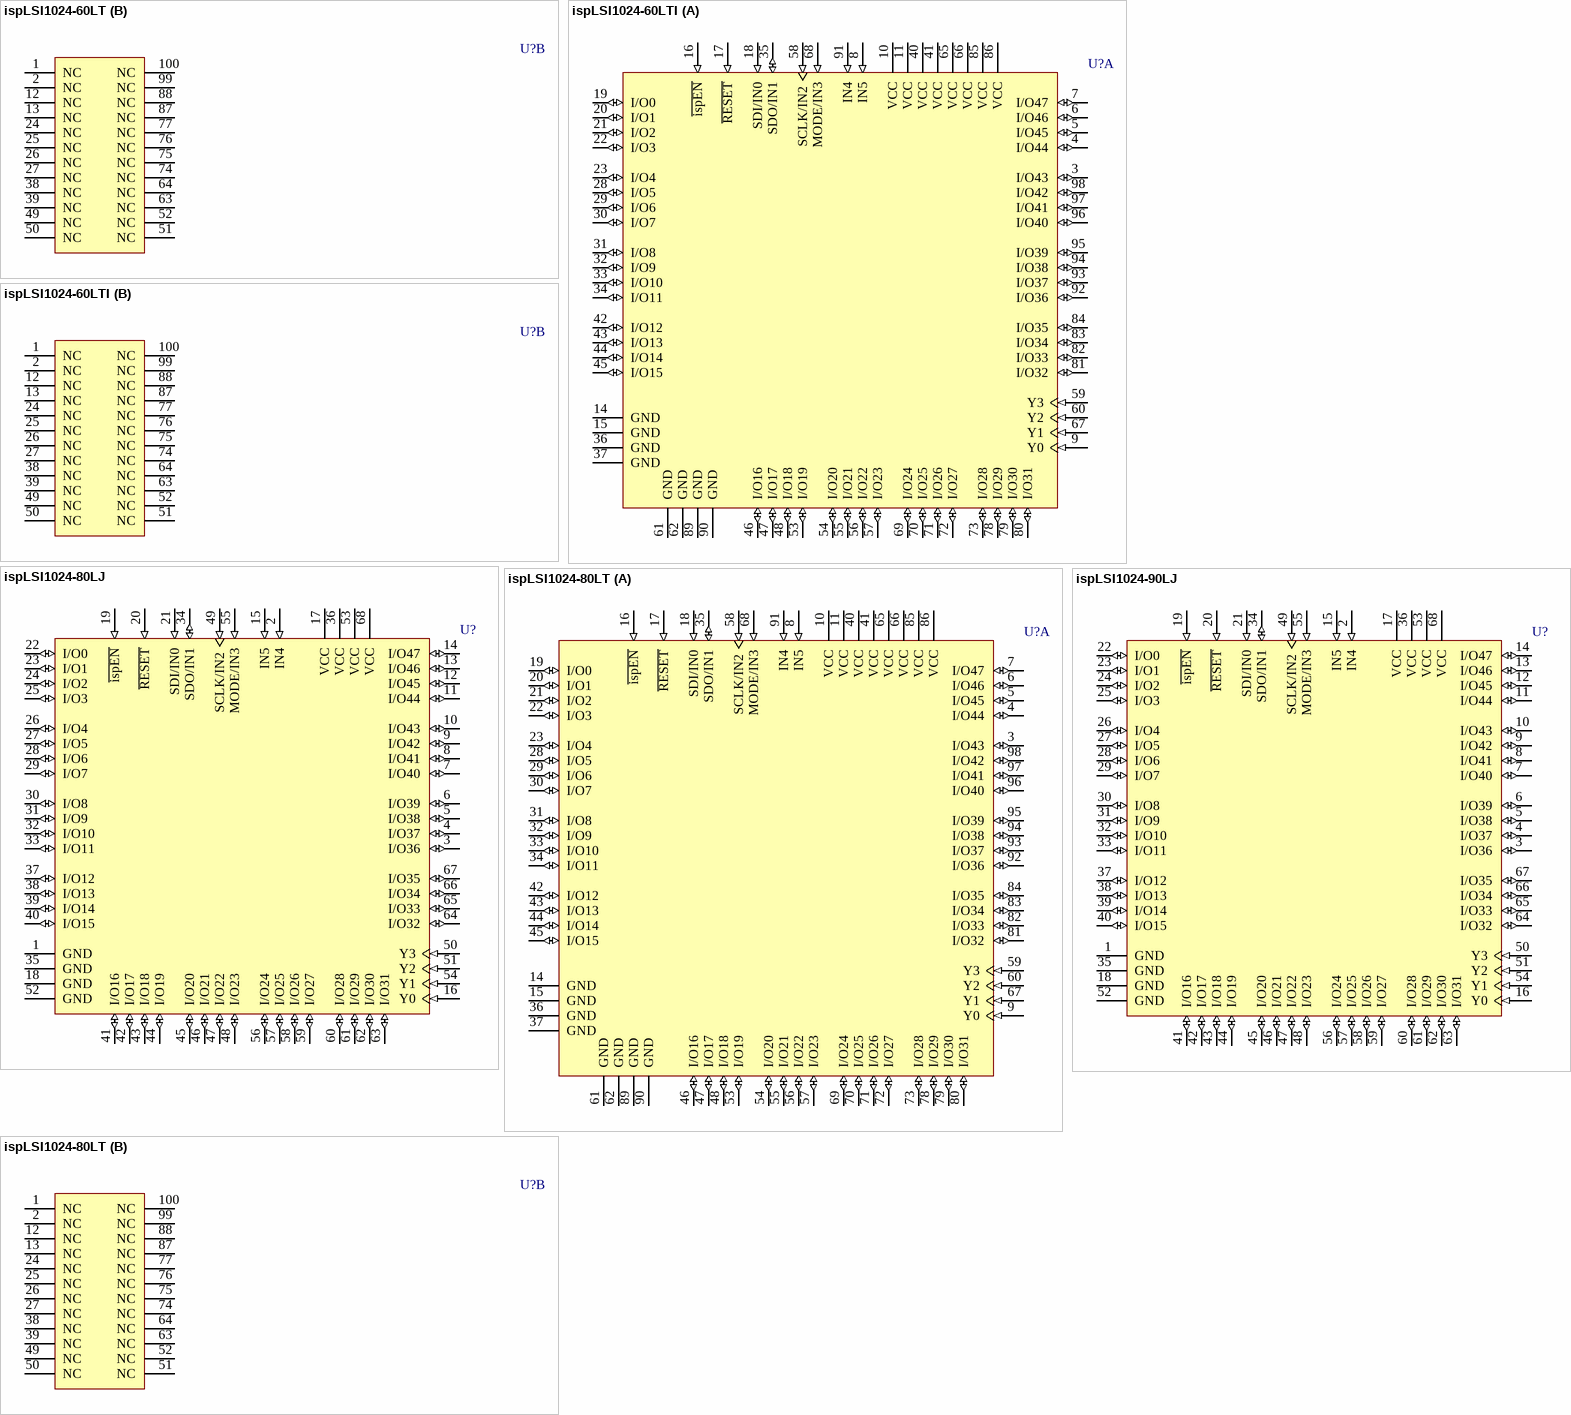
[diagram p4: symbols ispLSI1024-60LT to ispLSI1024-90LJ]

## ispLSI1024-60LT
designator U?
In-System Programmable High-Density PLD; Note: Pins 18, 35, 58 and 68 have dual function capability.; Note: NC pins are not to be connected to any active signal, VCC or GND.
footprint TQFP100_N (Thin QFP, 100-Leads, Body 14x14mm, Pitch 0.5mm, IPC Medium Density)
footprint TQFP100_L (Thin QFP, 100-Leads, Body 14x14mm, Pitch 0.5mm, IPC High Density)
footprint TQFP100_M (Thin QFP, 100-Leads, Body 14x14mm, Pitch 0.5mm, IPC Low Density)
3D model 1024-TQFP100 (100-Pin Thin Quad Flat Pack (TQFP100))
part A pins: 3 I/O43 (io), 4 I/O44 (io), 5 I/O45 (io), 6 I/O46 (io), 7 I/O47 (io), 8 IN5 (in), 9 Y0 (in), 10 VCC (power), 11 VCC (power), 14 GND (power), 15 GND (power), 16 ~{ispEN} (in), 17 ~{RESET} (in), 18 SDI/IN0 (in), 19 I/O0 (io), 20 I/O1 (io), 21 I/O2 (io), 22 I/O3 (io), 23 I/O4 (io), 28 I/O5 (io), 29 I/O6 (io), 30 I/O7 (io), 31 I/O8 (io), 32 I/O9 (io), 33 I/O10 (io), 34 I/O11 (io), 35 SDO/IN1 (io), 36 GND (power), 37 GND (power), 40 VCC (power), 41 VCC (power), 42 I/O12 (io), 43 I/O13 (io), 44 I/O14 (io), 45 I/O15 (io), 46 I/O16 (io), 47 I/O17 (io), 48 I/O18 (io), 53 I/O19 (io), 54 I/O20 (io), 55 I/O21 (io), 56 I/O22 (io), 57 I/O23 (io), 58 SCLK/IN2 (in), 59 Y3 (in), 60 Y2 (in), 61 GND (power), 62 GND (power), 65 VCC (power), 66 VCC (power), 67 Y1 (in), 68 MODE/IN3 (in), 69 I/O24 (io), 70 I/O25 (io), 71 I/O26 (io), 72 I/O27 (io), 73 I/O28 (io), 78 I/O29 (io), 79 I/O30 (io), 80 I/O31 (io), 81 I/O32 (io), 82 I/O33 (io), 83 I/O34 (io), 84 I/O35 (io), 85 VCC (power), 86 VCC (power), 89 GND (power), 90 GND (power), 91 IN4 (in), 92 I/O36 (io), 93 I/O37 (io), 94 I/O38 (io), 95 I/O39 (io), 96 I/O40 (io), 97 I/O41 (io), 98 I/O42 (io)
part B pins: 1 NC, 2 NC, 12 NC, 13 NC, 24 NC, 25 NC, 26 NC, 27 NC, 38 NC, 39 NC, 49 NC, 50 NC, 51 NC, 52 NC, 63 NC, 64 NC, 74 NC, 75 NC, 76 NC, 77 NC, 87 NC, 88 NC, 99 NC, 100 NC

## ispLSI1024-60LTI
designator U?
In-System Programmable High-Density PLD; Note: Pins 18, 35, 58 and 68 have dual function capability.; Note: NC pins are not to be connected to any active signal, VCC or GND.
footprint TQFP100_N (Thin QFP, 100-Leads, Body 14x14mm, Pitch 0.5mm, IPC Medium Density)
footprint TQFP100_L (Thin QFP, 100-Leads, Body 14x14mm, Pitch 0.5mm, IPC High Density)
footprint TQFP100_M (Thin QFP, 100-Leads, Body 14x14mm, Pitch 0.5mm, IPC Low Density)
3D model 1024-TQFP100 (100-Pin Thin Quad Flat Pack (TQFP100))
part A pins: 3 I/O43 (io), 4 I/O44 (io), 5 I/O45 (io), 6 I/O46 (io), 7 I/O47 (io), 8 IN5 (in), 9 Y0 (in), 10 VCC (power), 11 VCC (power), 14 GND (power), 15 GND (power), 16 ~{ispEN} (in), 17 ~{RESET} (in), 18 SDI/IN0 (in), 19 I/O0 (io), 20 I/O1 (io), 21 I/O2 (io), 22 I/O3 (io), 23 I/O4 (io), 28 I/O5 (io), 29 I/O6 (io), 30 I/O7 (io), 31 I/O8 (io), 32 I/O9 (io), 33 I/O10 (io), 34 I/O11 (io), 35 SDO/IN1 (io), 36 GND (power), 37 GND (power), 40 VCC (power), 41 VCC (power), 42 I/O12 (io), 43 I/O13 (io), 44 I/O14 (io), 45 I/O15 (io), 46 I/O16 (io), 47 I/O17 (io), 48 I/O18 (io), 53 I/O19 (io), 54 I/O20 (io), 55 I/O21 (io), 56 I/O22 (io), 57 I/O23 (io), 58 SCLK/IN2 (in), 59 Y3 (in), 60 Y2 (in), 61 GND (power), 62 GND (power), 65 VCC (power), 66 VCC (power), 67 Y1 (in), 68 MODE/IN3 (in), 69 I/O24 (io), 70 I/O25 (io), 71 I/O26 (io), 72 I/O27 (io), 73 I/O28 (io), 78 I/O29 (io), 79 I/O30 (io), 80 I/O31 (io), 81 I/O32 (io), 82 I/O33 (io), 83 I/O34 (io), 84 I/O35 (io), 85 VCC (power), 86 VCC (power), 89 GND (power), 90 GND (power), 91 IN4 (in), 92 I/O36 (io), 93 I/O37 (io), 94 I/O38 (io), 95 I/O39 (io), 96 I/O40 (io), 97 I/O41 (io), 98 I/O42 (io)
part B pins: 1 NC, 2 NC, 12 NC, 13 NC, 24 NC, 25 NC, 26 NC, 27 NC, 38 NC, 39 NC, 49 NC, 50 NC, 51 NC, 52 NC, 63 NC, 64 NC, 74 NC, 75 NC, 76 NC, 77 NC, 87 NC, 88 NC, 99 NC, 100 NC

## ispLSI1024-80LJ
designator U?
High-Density Programmable Logic
footprint PLCC68_N (Leaded Chip Carrier, 68-Leads, Body 24x24mm, Pitch 1.27mm, IPC Medium Density)
footprint PLCC68_L (Leaded Chip Carrier, 68-Leads, Body 24x24mm, Pitch 1.27mm, IPC High Density)
footprint PLCC68_M (Leaded Chip Carrier, 68-Leads, Body 24x24mm, Pitch 1.27mm, IPC Low Density)
3D model 1024-PLCC68 (68-Pin Leaded Chip Carrier 1.27 mm Pitch)
pins: 1 GND (power), 2 IN4 (in), 3 I/O36 (io), 4 I/O37 (io), 5 I/O38 (io), 6 I/O39 (io), 7 I/O40 (io), 8 I/O41 (io), 9 I/O42 (io), 10 I/O43 (io), 11 I/O44 (io), 12 I/O45 (io), 13 I/O46 (io), 14 I/O47 (io), 15 IN5 (in), 16 Y0 (in), 17 VCC (power), 18 GND (power), 19 ~{ispEN} (in), 20 ~{RESET} (in), 21 SDI/IN0 (in), 22 I/O0 (io), 23 I/O1 (io), 24 I/O2 (io), 25 I/O3 (io), 26 I/O4 (io), 27 I/O5 (io), 28 I/O6 (io), 29 I/O7 (io), 30 I/O8 (io), 31 I/O9 (io), 32 I/O10 (io), 33 I/O11 (io), 34 SDO/IN1 (io), 35 GND (power), 36 VCC (power), 37 I/O12 (io), 38 I/O13 (io), 39 I/O14 (io), 40 I/O15 (io), 41 I/O16 (io), 42 I/O17 (io), 43 I/O18 (io), 44 I/O19 (io), 45 I/O20 (io), 46 I/O21 (io), 47 I/O22 (io), 48 I/O23 (io), 49 SCLK/IN2 (in), 50 Y3 (in), 51 Y2 (in), 52 GND (power), 53 VCC (power), 54 Y1 (in), 55 MODE/IN3 (in), 56 I/O24 (io), 57 I/O25 (io), 58 I/O26 (io), 59 I/O27 (io), 60 I/O28 (io), 61 I/O29 (io), 62 I/O30 (io), 63 I/O31 (io), 64 I/O32 (io), 65 I/O33 (io), 66 I/O34 (io), 67 I/O35 (io), 68 VCC (power)

## ispLSI1024-80LT
designator U?
In-System Programmable High-Density PLD; Note: Pins 18, 35, 58 and 68 have dual function capability.; Note: NC pins are not to be connected to any active signal, VCC or GND.
footprint TQFP100_N (Thin QFP, 100-Leads, Body 14x14mm, Pitch 0.5mm, IPC Medium Density)
footprint TQFP100_L (Thin QFP, 100-Leads, Body 14x14mm, Pitch 0.5mm, IPC High Density)
footprint TQFP100_M (Thin QFP, 100-Leads, Body 14x14mm, Pitch 0.5mm, IPC Low Density)
3D model 1024-TQFP100 (100-Pin Thin Quad Flat Pack (TQFP100))
part A pins: 3 I/O43 (io), 4 I/O44 (io), 5 I/O45 (io), 6 I/O46 (io), 7 I/O47 (io), 8 IN5 (in), 9 Y0 (in), 10 VCC (power), 11 VCC (power), 14 GND (power), 15 GND (power), 16 ~{ispEN} (in), 17 ~{RESET} (in), 18 SDI/IN0 (in), 19 I/O0 (io), 20 I/O1 (io), 21 I/O2 (io), 22 I/O3 (io), 23 I/O4 (io), 28 I/O5 (io), 29 I/O6 (io), 30 I/O7 (io), 31 I/O8 (io), 32 I/O9 (io), 33 I/O10 (io), 34 I/O11 (io), 35 SDO/IN1 (io), 36 GND (power), 37 GND (power), 40 VCC (power), 41 VCC (power), 42 I/O12 (io), 43 I/O13 (io), 44 I/O14 (io), 45 I/O15 (io), 46 I/O16 (io), 47 I/O17 (io), 48 I/O18 (io), 53 I/O19 (io), 54 I/O20 (io), 55 I/O21 (io), 56 I/O22 (io), 57 I/O23 (io), 58 SCLK/IN2 (in), 59 Y3 (in), 60 Y2 (in), 61 GND (power), 62 GND (power), 65 VCC (power), 66 VCC (power), 67 Y1 (in), 68 MODE/IN3 (in), 69 I/O24 (io), 70 I/O25 (io), 71 I/O26 (io), 72 I/O27 (io), 73 I/O28 (io), 78 I/O29 (io), 79 I/O30 (io), 80 I/O31 (io), 81 I/O32 (io), 82 I/O33 (io), 83 I/O34 (io), 84 I/O35 (io), 85 VCC (power), 86 VCC (power), 89 GND (power), 90 GND (power), 91 IN4 (in), 92 I/O36 (io), 93 I/O37 (io), 94 I/O38 (io), 95 I/O39 (io), 96 I/O40 (io), 97 I/O41 (io), 98 I/O42 (io)
part B pins: 1 NC, 2 NC, 12 NC, 13 NC, 24 NC, 25 NC, 26 NC, 27 NC, 38 NC, 39 NC, 49 NC, 50 NC, 51 NC, 52 NC, 63 NC, 64 NC, 74 NC, 75 NC, 76 NC, 77 NC, 87 NC, 88 NC, 99 NC, 100 NC

## ispLSI1024-90LJ
designator U?
High-Density Programmable Logic
footprint PLCC68_N (Leaded Chip Carrier, 68-Leads, Body 24x24mm, Pitch 1.27mm, IPC Medium Density)
footprint PLCC68_L (Leaded Chip Carrier, 68-Leads, Body 24x24mm, Pitch 1.27mm, IPC High Density)
footprint PLCC68_M (Leaded Chip Carrier, 68-Leads, Body 24x24mm, Pitch 1.27mm, IPC Low Density)
3D model 1024-PLCC68 (68-Pin Leaded Chip Carrier 1.27 mm Pitch)
pins: 1 GND (power), 2 IN4 (in), 3 I/O36 (io), 4 I/O37 (io), 5 I/O38 (io), 6 I/O39 (io), 7 I/O40 (io), 8 I/O41 (io), 9 I/O42 (io), 10 I/O43 (io), 11 I/O44 (io), 12 I/O45 (io), 13 I/O46 (io), 14 I/O47 (io), 15 IN5 (in), 16 Y0 (in), 17 VCC (power), 18 GND (power), 19 ~{ispEN} (in), 20 ~{RESET} (in), 21 SDI/IN0 (in), 22 I/O0 (io), 23 I/O1 (io), 24 I/O2 (io), 25 I/O3 (io), 26 I/O4 (io), 27 I/O5 (io), 28 I/O6 (io), 29 I/O7 (io), 30 I/O8 (io), 31 I/O9 (io), 32 I/O10 (io), 33 I/O11 (io), 34 SDO/IN1 (io), 35 GND (power), 36 VCC (power), 37 I/O12 (io), 38 I/O13 (io), 39 I/O14 (io), 40 I/O15 (io), 41 I/O16 (io), 42 I/O17 (io), 43 I/O18 (io), 44 I/O19 (io), 45 I/O20 (io), 46 I/O21 (io), 47 I/O22 (io), 48 I/O23 (io), 49 SCLK/IN2 (in), 50 Y3 (in), 51 Y2 (in), 52 GND (power), 53 VCC (power), 54 Y1 (in), 55 MODE/IN3 (in), 56 I/O24 (io), 57 I/O25 (io), 58 I/O26 (io), 59 I/O27 (io), 60 I/O28 (io), 61 I/O29 (io), 62 I/O30 (io), 63 I/O31 (io), 64 I/O32 (io), 65 I/O33 (io), 66 I/O34 (io), 67 I/O35 (io), 68 VCC (power)

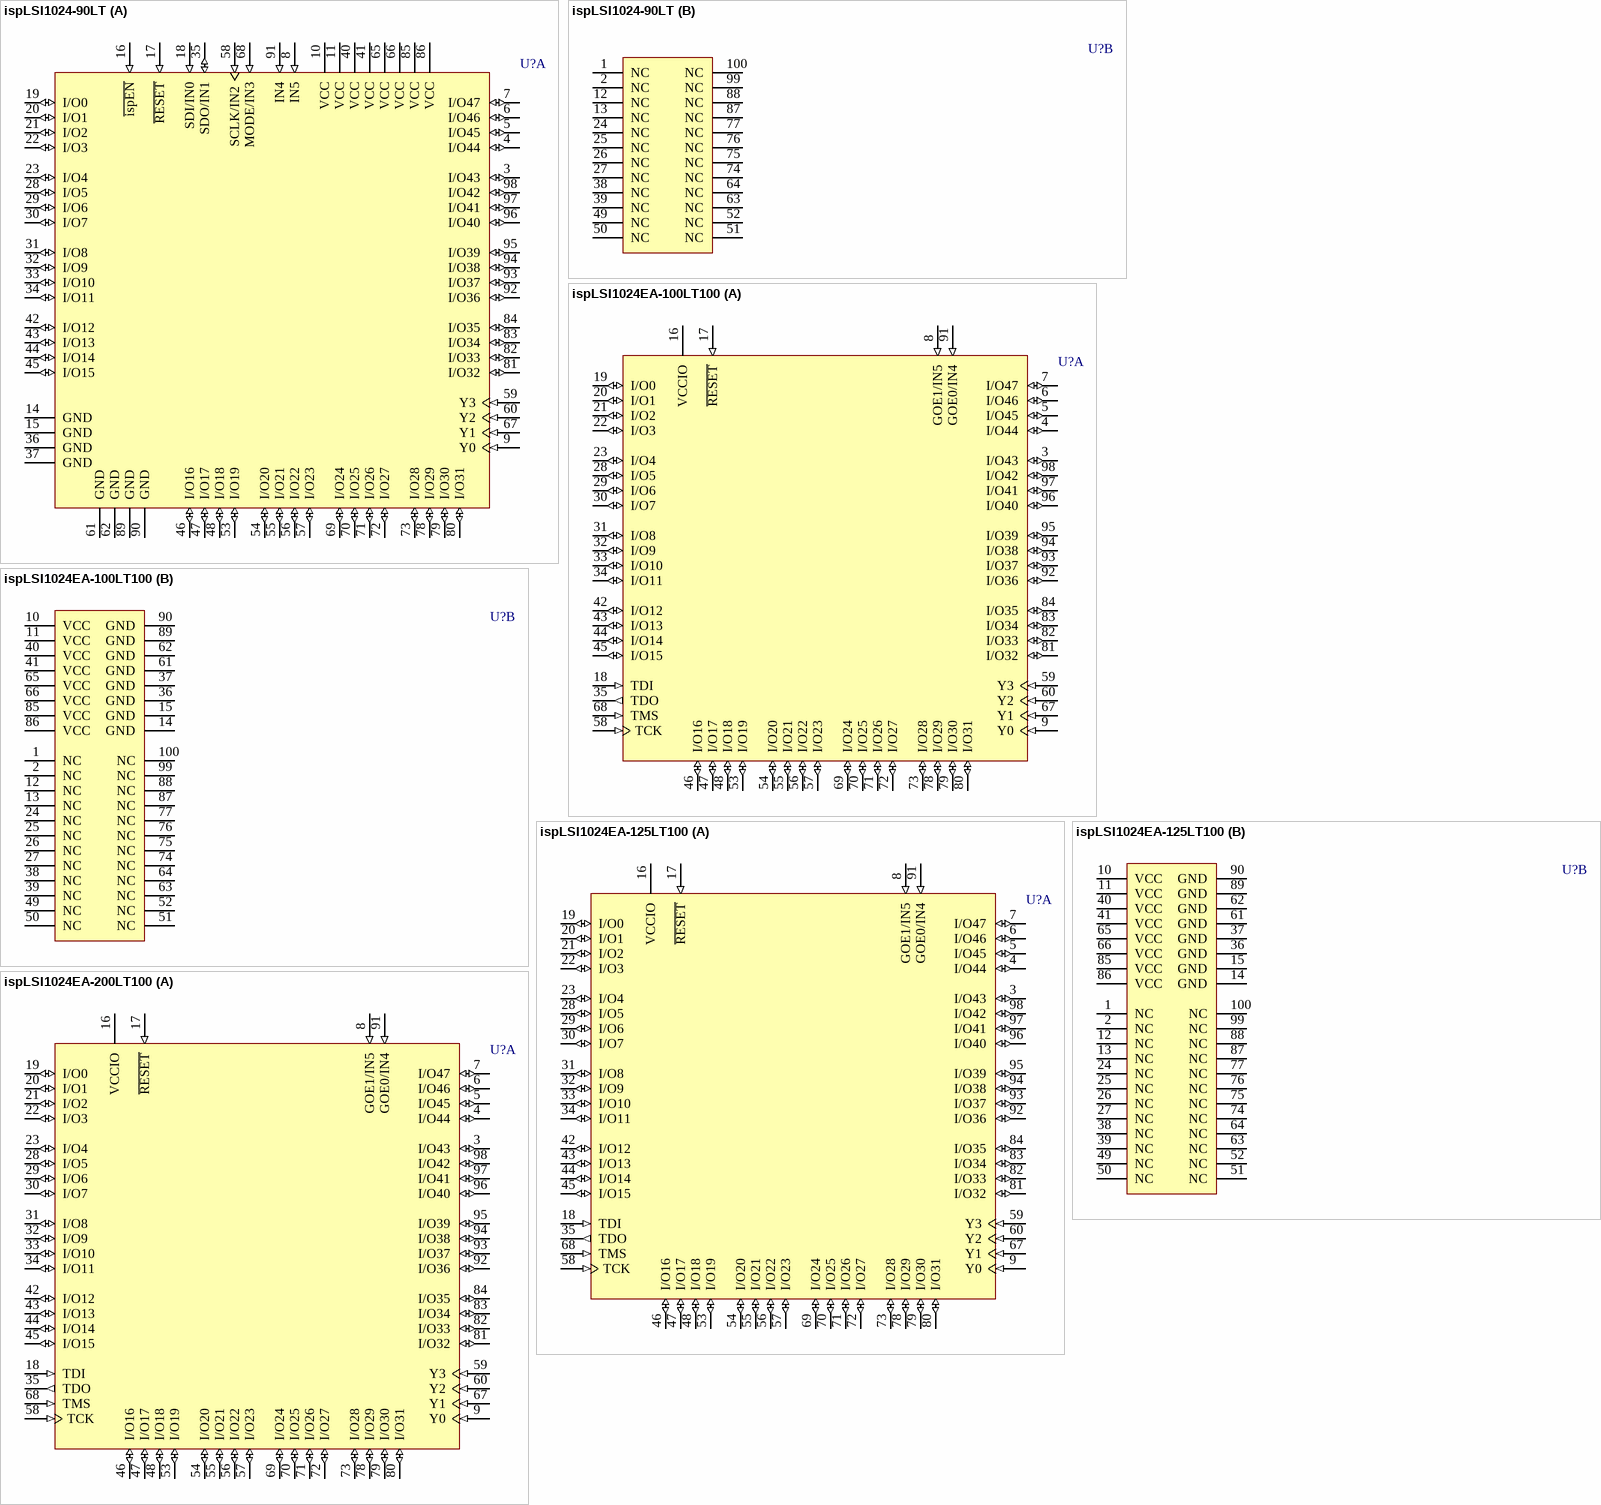
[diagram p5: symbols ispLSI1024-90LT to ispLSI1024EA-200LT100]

## ispLSI1024-90LT
designator U?
In-System Programmable High-Density PLD; Note: Pins 18, 35, 58 and 68 have dual function capability.; Note: NC pins are not to be connected to any active signal, VCC or GND.
footprint TQFP100_N (Thin QFP, 100-Leads, Body 14x14mm, Pitch 0.5mm, IPC Medium Density)
footprint TQFP100_L (Thin QFP, 100-Leads, Body 14x14mm, Pitch 0.5mm, IPC High Density)
footprint TQFP100_M (Thin QFP, 100-Leads, Body 14x14mm, Pitch 0.5mm, IPC Low Density)
3D model 1024-TQFP100 (100-Pin Thin Quad Flat Pack (TQFP100))
part A pins: 3 I/O43 (io), 4 I/O44 (io), 5 I/O45 (io), 6 I/O46 (io), 7 I/O47 (io), 8 IN5 (in), 9 Y0 (in), 10 VCC (power), 11 VCC (power), 14 GND (power), 15 GND (power), 16 ~{ispEN} (in), 17 ~{RESET} (in), 18 SDI/IN0 (in), 19 I/O0 (io), 20 I/O1 (io), 21 I/O2 (io), 22 I/O3 (io), 23 I/O4 (io), 28 I/O5 (io), 29 I/O6 (io), 30 I/O7 (io), 31 I/O8 (io), 32 I/O9 (io), 33 I/O10 (io), 34 I/O11 (io), 35 SDO/IN1 (io), 36 GND (power), 37 GND (power), 40 VCC (power), 41 VCC (power), 42 I/O12 (io), 43 I/O13 (io), 44 I/O14 (io), 45 I/O15 (io), 46 I/O16 (io), 47 I/O17 (io), 48 I/O18 (io), 53 I/O19 (io), 54 I/O20 (io), 55 I/O21 (io), 56 I/O22 (io), 57 I/O23 (io), 58 SCLK/IN2 (in), 59 Y3 (in), 60 Y2 (in), 61 GND (power), 62 GND (power), 65 VCC (power), 66 VCC (power), 67 Y1 (in), 68 MODE/IN3 (in), 69 I/O24 (io), 70 I/O25 (io), 71 I/O26 (io), 72 I/O27 (io), 73 I/O28 (io), 78 I/O29 (io), 79 I/O30 (io), 80 I/O31 (io), 81 I/O32 (io), 82 I/O33 (io), 83 I/O34 (io), 84 I/O35 (io), 85 VCC (power), 86 VCC (power), 89 GND (power), 90 GND (power), 91 IN4 (in), 92 I/O36 (io), 93 I/O37 (io), 94 I/O38 (io), 95 I/O39 (io), 96 I/O40 (io), 97 I/O41 (io), 98 I/O42 (io)
part B pins: 1 NC, 2 NC, 12 NC, 13 NC, 24 NC, 25 NC, 26 NC, 27 NC, 38 NC, 39 NC, 49 NC, 50 NC, 51 NC, 52 NC, 63 NC, 64 NC, 74 NC, 75 NC, 76 NC, 77 NC, 87 NC, 88 NC, 99 NC, 100 NC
